// TIA Portal project "ISC_COMM_PROFINET_V15.1_rev1" (V15.1)
// Example of PLC to ISC-CAM communication.

(* hardware
DEVICE "S7-1200 station_1"  S7-1200 Station
   slot 0: "Rack_0"  S7-1200 Rack  Rack  V1.0
   slot 1: "LinePLC1"  CPU 1215C DC/DC/DC  6ES7 215-1AG40-0XB0  V4.2
DEVICE "ISC-CAM"  GSD.Device.PN
   slot 0: "Rack"  Rack  V1.0
   slot 0: "ISC-CAM_145"  Business Logic PN Device  SW V 1.6.3
      slot 0: "DAP v3.1"  DAP v3.1
      slot 1: "PN-IO"  PN-IO
         slot 1: "Port 1"  Port 1
         slot 2: "Port 2"  Port 2
   slot 1: "IN 48 WORD"  IN 48 WORD
      slot 0: "IN 48 WORD"  IN 48 WORD
   slot 2: "OUT 16 WORD"  OUT 16 WORD
      slot 0: "OUT 16 WORD"  OUT 16 WORD
DEVICE "ISC-CAM_1"  GSD.Device.PN
   slot 0: "Rack"  Rack  V1.0
   slot 0: "ISC-CAM_146"  Business Logic PN Device  SW V 1.6.3
      slot 0: "DAP v3.1"  DAP v3.1
      slot 1: "PN-IO"  PN-IO
         slot 1: "Port 1"  Port 1
         slot 2: "Port 2"  Port 2
   slot 1: "IN 48 WORD"  IN 48 WORD
      slot 0: "IN 48 WORD"  IN 48 WORD
   slot 2: "OUT 16 WORD"  OUT 16 WORD
      slot 0: "OUT 16 WORD"  OUT 16 WORD
*)

// ===== PLC "LinePLC1"  CPU 1215C DC/DC/DC =====

VAR_GLOBAL   // PLC tag table "Default tag table"
   "Sim_EncoderOutput(0)" AT %Q0.0 : Bool;
   "Sim_PEOutput(0)" AT %Q0.1 : Bool;
   "System_Byte" AT %MB1 : Byte;
   "FirstScan" AT %M1.0 : Bool;
   "DiagStatusUpdate" AT %M1.1 : Bool;
   "AlwaysTRUE" AT %M1.2 : Bool;
   "AlwaysFALSE" AT %M1.3 : Bool;
   "Clock_Byte" AT %MB0 : Byte;
   "Clock_10Hz" AT %M0.0 : Bool;
   "Clock_5Hz" AT %M0.1 : Bool;
   "Clock_2.5Hz" AT %M0.2 : Bool;
   "Clock_2Hz" AT %M0.3 : Bool;
   "Clock_1.25Hz" AT %M0.4 : Bool;
   "Clock_1Hz" AT %M0.5 : Bool;
   "Clock_0.625Hz" AT %M0.6 : Bool;
   "Clock_0.5Hz" AT %M0.7 : Bool;
   "Sim_EncoderOutput(1)" AT %Q0.2 : Bool;
   "Sim_PEOutput(1)" AT %Q0.3 : Bool;
END_VAR

VAR_GLOBAL CONSTANT   // PLC tag table "Default tag table"
   "ParameterNr" : DInt := 13;   // Number of parameters + 1
   "RecipeNr" : DInt := 3;   // Number of recipes + 1
END_VAR

TYPE "dt_ISCCAM"
   STRUCT
      Command : "dt_ISCCAM_Cmd";
      Status : "dt_ISCCAM_Stat";
      Parameter : "dt_ISCCAM_Parameter";
      Datacollection : "dt_ISCCAM_Datacollection";
      CommunicationHealthy : Bool;
   END_STRUCT;
END_TYPE

TYPE "dt_ISCCAM_Cmd"
   STRUCT
      LifeBit : Bool;   // Lifebit
      Reset_Error : Bool;   // Reset error
      MotorRunning : Bool;   // Motor running
      ProductsFromInfeed2 : Bool;   // Products from infeed 2
      AssignDestination : Int;   // Assign destination
      ExternalModel : Bool;   // External model
      Exit1BalancingSet : Int;   // Set balancing exit 1
      Exit2BalancingSet : Int;   // Set balancing exit 2
      Exit3BalancingSet : Int;   // Set balancing exit 3
      EndBalancingSet : Int;   // Set balancing end
      DES_Enable1 : Bool;   // Enable destination 1
      DES_Enable2 : Bool;   // Enable destination 2
      DES_Enable3 : Bool;   // Enable destination 3
   END_STRUCT;
END_TYPE

TYPE "dt_ISCCAM_Datacollection"
   STRUCT
      BeltRunTime : DInt;   // Cumulative time the belt is moving [min]
      BeltTravelDistance : DInt;   // Cumulative distance the belt has traveled [m]
      "ActivationCount Zone0" : DInt;   // Cumulative number of activations divert zone 0
      "ActivationCount Zone1" : DInt;   // Cumulative number of activations divert zone 1
      "ActivationCount Zone2" : DInt;   // Cumulative number of activations divert zone 2
      ProductCount : DInt;   // Cumulative number of products on the belt
      StartStops : DInt;   // Cumulative number of start stops of the belt
      GapToSmallCount : DInt;   // Cumulative number a too small gap was detected
      FaultCount : Int;   // A counter that keeps track of how many faults were detected
      MaxBeltSpeed : Int;   // The maximum belt speed that has been detected [m/min]
      PeakAcceleration : Int;   // Peak acceleration [m/min2]
      PeakDecceleration : Int;   // Peak decceleration [m/min2]
   END_STRUCT;
END_TYPE

TYPE "dt_ISCCAM_FaultCode"
   STRUCT
      "FaultCode.8" : Bool;   // Peg not seen when expected
      "FaultCode.9" : Bool;   // Gap for next product
      "FaultCode.10" : Bool;   // Too much or too low voltage from power supply
      "FaultCode.11" : Bool;   // IO Current fault. Input too high or too low (indicates short or cable disconnected)
      "FaultCode.12" : Bool;   // IO-Link error port C0
      "FaultCode.13" : Bool;   // IO-Link error port C1
      "FaultCode.14" : Bool;   // IO-Link error port C2
      "FaultCode.15" : Bool;   // IO-Link error port C3
      "FaultCode.0" : Bool;   // Line controller PLC indicated the drive motor is running, but the encoder does not detect motion
      "FaultCode.1" : Bool;   // Line controller PLC indicates the drive motor is off, but the encoder detects belt motion
      "FaultCode.2" : Bool;   // Belt detected to move too slow (and not stopped)
      "FaultCode.3" : Bool;   // Belt detected to move too fast
      "FaultCode.4" : Bool;   // Status of photoeye Product Sensor 1
      "FaultCode.5" : Bool;   // Status of photoeye Product Sensor 2 (Optional)
      "FaultCode.6" : Bool;   // Status of photoeye Product Sensor 3 (Optional)
      "FaultCode.7" : Bool;   // Peg sensor blocked continuously with belt moving
      "FaultCode.24" : Bool;
      "FaultCode.25" : Bool;
      "FaultCode.26" : Bool;
      "FaultCode.27" : Bool;
      "FaultCode.28" : Bool;
      "FaultCode.29" : Bool;
      "FaultCode.30" : Bool;
      "FaultCode.31" : Bool;
      "FaultCode.16" : Bool;
      "FaultCode.17" : Bool;
      "FaultCode.18" : Bool;
      "FaultCode.19" : Bool;
      "FaultCode.20" : Bool;
      "FaultCode.21" : Bool;
      "FaultCode.22" : Bool;
      "FaultCode.23" : Bool;
   END_STRUCT;
END_TYPE

TYPE "dt_ISCCAM_IO_Status"
   STRUCT
      "IO Status.8" : Bool;
      "IO Status.9" : Bool;
      "IO Status.10" : Bool;
      "IO Status.11" : Bool;
      "IO Status.12" : Bool;
      "IO Status.13" : Bool;
      "IO Status.14" : Bool;
      "IO Status.15" : Bool;
      "IO Status.0" : Bool;
      "IO Status.1" : Bool;   // Product sensor
      "IO Status.2" : Bool;   // Peg sensor divert 1 (AIM only)
      "IO Status.3" : Bool;   // Valve divert 1
      "IO Status.4" : Bool;   // Peg sensor divert 2 (AIM only)
      "IO Status.5" : Bool;   // Valve divert 2
      "IO Status.6" : Bool;   // Discrete divert Signal
      "IO Status.7" : Bool;   // Run/Error
   END_STRUCT;
END_TYPE

TYPE "dt_ISCCAM_Parameter"
   STRUCT
      Cmd : "dt_ISCCAM_Parameter_Cmd";
      Stat : "dt_ISCCAM_Parameter_Stat";
   END_STRUCT;
END_TYPE

TYPE "dt_ISCCAM_Parameter_Cmd"
   STRUCT
      ParameterNumber : Int;   // Parameter number f or read / write access.
      ParameterData : DWord;   // Parameter data f or write access.
      ReadTrigger : Bool;   // Read trigger.
      WriteTrigger : Bool;   // Write trigger.
   END_STRUCT;
END_TYPE

TYPE "dt_ISCCAM_Parameter_Stat"
   STRUCT
      ParameterNumber : Int;   // Parameter number feedback
      ParameterData : DWord;   // Parameter data
      ParameterReadSuccessfully : Bool;   // Parameter read successfully
      ParameterWriteSuccessfully : Bool;   // Parameter write successfully
      ParameterNumberNotExistReadOnly : Bool;   // Parameter number does not exist or is read only
      ParameterValueOutOfRange : Bool;   // Parameter value out of range
   END_STRUCT;
END_TYPE

TYPE "dt_ISCCAM_PI"
   STRUCT
      Status : "dt_ISCCAM_PI_Status";
      DataCollection1 : "dt_ISCCAM_PI_DataCollection_1";
      DataCollection2 : "dt_ISCCAM_PI_DataCollection_2";
   END_STRUCT;
END_TYPE

TYPE "dt_ISCCAM_PI_DataCollection_1"
   STRUCT
      BeltRunTime_MSW : Word;   // Cumulative time the belt is moving [min] HiWord
      BeltRunTime_LSW : Word;   // Cumulative time the belt is moving [min] LoWord
      BeltTravelDistance_MSW : Word;   // Cumulative distance the belt has traveled [m] HiWord
      BeltTravelDistance_LSW : Word;   // Cumulative distance the belt has traveled [m] LoWord
      ActivationCount_Zone0_MSW : Word;   // Cumulative number of activations divert zone 0 HiWord
      ActivationCount_Zone0_LSW : Word;   // Cumulative number of activations divert zone 0 LoWord
      ActivationCount_Zone1_MSW : Word;   // Cumulative number of activations divert zone 1 HiWord
      ActivationCount_Zone1_LSW : Word;   // Cumulative number of activations divert zone 1 LoWord
      ActivationCount_Zone2_MSW : Word;   // Cumulative number of activations divert zone 2 HiWord
      ActivationCount_Zone2_LSW : Word;   // Cumulative number of activations divert zone 2 LoWord
      ProductCount_MSW : Word;   // Cumulative number of products on the belt HiWord
      ProductCount_LSW : Word;   // Cumulative number of products on the belt LoWord
      StartStops_MSW : Word;   // Cumulative number of start stops of the belt HiWord
      StartStops_LSW : Word;   // Cumulative number of start stops of the belt LoWord
      GapToSmallCount_MSW : Word;   // Cumulative number a too small gap was detected HiWord
      GapToSmallCount_LSW : Word;   // Cumulative number a too small gap was detected LoWord
   END_STRUCT;
END_TYPE

TYPE "dt_ISCCAM_PI_DataCollection_2"
   STRUCT
      FaultCount : Word;   // A counter that keeps track of how many faults were detected
      MaxBeltSpeed : Word;   // The maximum belt speed that has been detected [m/min]
      PeakAcceleration : Word;   // Peak acceleration [m/min2]
      PeakDecceleration : Word;   // Peak decceleration [m/min2]
   END_STRUCT;
END_TYPE

TYPE "dt_ISCCAM_PI_Status"
   STRUCT
      EncoderStatus : Bool;   // Belt encoder pulses
      W0b9 : Bool;
      W0b10 : Bool;
      W0b11 : Bool;
      W0b12 : Bool;
      W0b13 : Bool;
      W0b14 : Bool;
      W0b15 : Bool;
      Life_Bit : Bool;   // Life bit / Heartbeat / Watchdog
      SystemReady : Bool;   // System Ready (no fault)
      W0b2 : Bool;
      W0b3 : Bool;
      Error : Bool;   // Error in Machine
      W0b5 : Bool;
      W0b6 : Bool;
      W0b7 : Bool;
      FaultCode : DWord;   // FaultCode
      ProductsOnBelt : Word;   // Count of current products on the belt
      Throughput : Word;   // Products on DPE
      BeltSpeed : Word;   // Current speed of the belt [m/min]
      BeltAcceleration : Word;   // Acceleration speed of the belt [m/min2]
      "IO Status" : Word;   // IO Status
      W8 : Word;
      "PowerON MSW" : Word;   // Time since the ISC is powered on [sec] HiWord
      "PowerON LSW" : Word;   // Time since the ISC is powered on [sec] LoWord
      W11 : Word;
      "Parameter number feedback" : Word;   // Parameter number
      W13b8 : Bool;
      W13b9 : Bool;
      W13b10 : Bool;
      W13b11 : Bool;
      W13b12 : Bool;
      W13b13 : Bool;
      W13b14 : Bool;
      W13b15 : Bool;
      "Parameter read successfully" : Bool;   // Parameter read ok
      "Parameter write successfully" : Bool;   // Parameter write ok
      "Parameter number not exist or read only" : Bool;   // Parameter ID number incorrect or read only
      "Parameter value is out of range" : Bool;   // Parameter value incorrect
      W13b4 : Bool;
      W13b5 : Bool;
      W13b6 : Bool;
      W13b7 : Bool;
      "Parameter data register High Word" : Word;   // Parameter Data MSW
      "Parameter data register Low Word" : Word;   // Parameter Data MSW
   END_STRUCT;
END_TYPE

TYPE "dt_ISCCAM_PO"
   STRUCT
      Command : "dt_ISCCAM_PO_Command";
   END_STRUCT;
END_TYPE

TYPE "dt_ISCCAM_PO_Command"
   STRUCT
      W0b8 : Bool;
      W0b9 : Bool;
      W0b10 : Bool;
      W0b11 : Bool;
      W0b12 : Bool;
      ProductsFromInfeed2 : Bool;   // Products from infeed 2
      W0b14 : Bool;
      W0b15 : Bool;
      Life_Bit : Bool;   // Life bit
      MotorRunning : Bool;   // Motor is running
      W0b2 : Bool;
      W0b3 : Bool;
      W0b4 : Bool;
      W0b5 : Bool;
      W0b6 : Bool;
      Reset_Error : Bool;   // Reset all errors
      "Divert destination" : Word;   // Divert destination of the next product that will be arriving on the belt (external mode only)
      RunMode : Word;   // Internal mode [0] or external mode [1]
      ProductCountExit0 : Word;   // Number of products to exit (internal mode only)
      ProductCountExit1 : Word;   // Number of products to exit (internal mode only)
      ProductCountExit2 : Word;   // Number of products to exit (internal mode only)
      ProductCountExit3 : Word;   // Number of products to exit (internal mode only)
      W7b8 : Bool;
      W7b9 : Bool;
      W7b10 : Bool;
      W7b11 : Bool;
      W7b12 : Bool;
      W7b13 : Bool;
      W7b14 : Bool;
      W7b15 : Bool;
      "Enable exit 1" : Bool;   // Destination Enable/Disable
      "Enable exit 2" : Bool;   // Destination Enable/Disable
      "Enable exit 3" : Bool;   // Destination Enable/Disable
      W7b3 : Bool;
      W7b4 : Bool;
      W7b5 : Bool;
      W7b6 : Bool;
      W7b7 : Bool;
      W8 : Word;
      W9 : Word;
      W10 : Word;
      W11 : Word;
      "Parameter number for read / write access" : Word;   // Parameter number
      W13b8 : Bool;
      W13b9 : Bool;
      W13b10 : Bool;
      W13b11 : Bool;
      W13b12 : Bool;
      W13b13 : Bool;
      W13b14 : Bool;
      W13b15 : Bool;
      "Read Parameter" : Bool;   // Read parameter
      "Write Parameter" : Bool;   // Write parameter
      W13b2 : Bool;
      W13b3 : Bool;
      W13b4 : Bool;
      W13b5 : Bool;
      W13b6 : Bool;
      W13b7 : Bool;
      "Parameter data register High Word" : Word;   // Parameter Data MSW
      "Parameter data register Low Word" : Word;   // Parameter Data LSW
   END_STRUCT;
END_TYPE

TYPE "dt_ISCCAM_Stat"
   STRUCT
      LifeBit : Bool;   // Lifebit
      SystemReady : Bool;   // System ready
      Error : Bool;   // Error
      FaultCode : "dt_ISCCAM_FaultCode";   // Fault code
      ProductsOnBelt : Int;   // Products on belt
      Throughput : Int;   // Throughput
      BeltSpeed : Int;   // Belt speed
      BeltAcceleration : Int;   // Belt acceleration
      IOstatus : "dt_ISCCAM_IO_Status";   // IO status
      UpTime : DInt;   // Up time in min
   END_STRUCT;
END_TYPE

TYPE "dt_ISCCAM_Alarms"
   STRUCT
      CommsAlarm : Bool;   // Communication to ISC not healthy.
      Fault8Alarm : Bool;   // Peg not seen when expected
      Fault9Alarm : Bool;   // Gap for next product
      Fault10Alarm : Bool;   // Too much or too low voltage from power supply
      Fault11Alarm : Bool;   // IO Current fault, input too high or too low (indicates short or cable disconnected)
      Fault12Alarm : Bool;   // IO-Link error port C0
      Fault13Alarm : Bool;   // IO-Link error port C1
      Fault14Alarm : Bool;   // IO-Link error port C2
      Fault15Alarm : Bool;   // IO-Link error port C3
      Fault0Alarm : Bool;   // Line controller PLC indicated the motor is running. But the encoder does not detect motion
      Fault1Alarm : Bool;   // Line controller PLC indicates the drive motor is off, but the encoder detects belt motion
      Fault2Alarm : Bool;   // Belt detected to move too slow (and not stopped)
      Fault3Alarm : Bool;   // Belt detected to move too fast
      Fault4Alarm : Bool;   // Status of photoeye Product Sensor 1
      Fault5Alarm : Bool;   // Status of photoeye Product Sensor 2 (Optional)
      Fault6Alarm : Bool;   // Status of photoeye Product Sensor 3 (Optional)
      Fault7Alarm : Bool;   // Peg sensor blocked continuously with belt moving
   END_STRUCT;
END_TYPE

TYPE "dt_ISCCAM_Maintenance"
   STRUCT
      Counters : Array[0..15] of "dt_ISCCAM_MaintenanceCounter";
   END_STRUCT;
   // // Counters[0] : Belt run time - belt elongation.
   // // Counters[1] : Belt run time - belt contaminants.
   // // Counters[2] : Belt run time - wearstrip thickness.
   // // Counters[3] : Belt run time - helix rollers.
   // // Counters[4] : Belt run time - transfer rollers.
   // // Counters[5] : Belt run time - return rollers.
   // // Counters[6] : Belt run time - oil level drive motor.
   // // Counters[7] : Belt run time - cylinder movement, wear and contaminants, zone 0
   // // Counters[8] : Belt run time - cylinder movement, wear and contaminants, zone 1
   // // Counters[9] : Belt run time - cylinder movement, wear and contaminants, zone 2
   // // Counters[10] : Belt run time - pneumatic system check.
   // // Counters[11] : Spare
   // // Counters[12] : Spare
   // // Counters[13] : Spare
   // // Counters[14] : Spare
   // // Counters[15] : Spare
END_TYPE

TYPE "dt_ISCCAM_MaintenanceCounter"
   STRUCT
      Reset : Bool;   // Reset warning
      WarningBit : Bool;   // Warning active
      MaintenanceThreshold : DInt;   // Threshold to create warning [h]
      MaintenanceCountUnitlNextMaintenance : DInt;   // Count until next maintenance [min]
   END_STRUCT;
END_TYPE

// folder: Recipe

TYPE "dt_Rec_ISCCAM_Parameter"
   STRUCT
      ID : Int;
      Description : String;
   END_STRUCT;
END_TYPE

TYPE "dt_Rec_ISCCAM_Recipe"
   STRUCT
      "Name" : String;
      Parameter : Array[0.."ParameterNr"] of "dt_Rec_ISCCAM_Recipe_Parameter";
   END_STRUCT;
END_TYPE

TYPE "dt_Rec_ISCCAM_Recipe_Header"
   STRUCT
      "Name" : String;
      Number : DInt;
   END_STRUCT;
END_TYPE

TYPE "dt_Rec_ISCCAM_Recipe_Parameter"
   STRUCT
      ID : Int;
      "Name" : String;
      Description : String;
      Value : DInt;
   END_STRUCT;
END_TYPE

TYPE "dt_Rec_M001_Recipe"
   STRUCT
      Header : "dt_Rec_ISCCAM_Recipe_Header";
      Machine_001 : "dt_Rec_Machine_Recipe_Parameter";
   END_STRUCT;
END_TYPE

TYPE "dt_Rec_M002_Recipe"
   STRUCT
      Header : "dt_Rec_ISCCAM_Recipe_Header";
      Machine_002 : "dt_Rec_Machine_Recipe_Parameter";
   END_STRUCT;
END_TYPE

TYPE "dt_Rec_Machine_Recipe_Parameter"
   STRUCT
      Parameter : Array[0.."ParameterNr"] of "dt_Rec_ISCCAM_Recipe_Parameter";
   END_STRUCT;
END_TYPE

TYPE "dt_Rec_Recipe"
   STRUCT
      Header : "dt_Rec_ISCCAM_Recipe_Header";
      M001 : "dt_Rec_Machine_Recipe_Parameter";
      M002 : "dt_Rec_Machine_Recipe_Parameter";
   END_STRUCT;
END_TYPE

// folder: (top level)

DATA_BLOCK "DB_Global"   // DB4
{ S7_Optimized_Access := 'TRUE' }
VERSION : 0.1
   VAR
      InitRecipe : Bool;
      myLADDR : Hw_IoSystem;
      myMODE : UInt;
      returnValue : Int;
      mySTATE : Array[0..1023] of Bool;
   END_VAR
BEGIN
END_DATA_BLOCK

// folder: 000-099_General

DATA_BLOCK "iDB_General_Diagnostics"   // DB2
{ S7_Optimized_Access := 'TRUE' }
VERSION : 0.1
"General_Diagnostics"
BEGIN
END_DATA_BLOCK

DATA_BLOCK "iDB_General_Main"   // DB3
{ S7_Optimized_Access := 'TRUE' }
VERSION : 0.1
"General_Main"
BEGIN
END_DATA_BLOCK

DATA_BLOCK "DB_General_HMI"   // DB8
{ S7_Optimized_Access := 'TRUE' }
VERSION : 0.1
   VAR
      GeneralDateTimePLC : DTL;
      GeneralHmiSNPointer : Array[0..4] of Word;
      GeneralHMIScreenNumber : Int;
      GeneralFaultBits : Array[0..7] of Word;
      GeneralFaultGroupBits : Word;
      GeneralFault : Bool;
      GeneralAlarmBtnCol : Int;
      GeneralResetBtnCmd : Bool;
      AlarmBtnCol : Int;
      MaintenanceBtnCol : Int;
   END_VAR
BEGIN
END_DATA_BLOCK

// folder: 100-199_Machine_001

DATA_BLOCK "DB_M001_Status"   // DB11
{ S7_Optimized_Access := 'TRUE' }
VERSION : 0.1
   VAR
      "ISC-CAM" : "dt_ISCCAM";
   END_VAR
BEGIN
END_DATA_BLOCK

DATA_BLOCK "DB_M001_HMI"   // DB12
{ S7_Optimized_Access := 'TRUE' }
VERSION : 0.1
   VAR
      FaultBits : "dt_ISCCAM_Alarms";
      Fault : Bool;   // Any fault present
      MaintenanceCounters : "dt_ISCCAM_Maintenance";
   END_VAR
BEGIN
END_DATA_BLOCK

DATA_BLOCK "iDB_M001_Main"   // DB13
{ S7_Optimized_Access := 'TRUE' }
VERSION : 0.1
"M001_Main"
BEGIN
END_DATA_BLOCK

// folder: 200-299_Machine_002

DATA_BLOCK "DB_M002_Status"   // DB5
{ S7_Optimized_Access := 'TRUE' }
VERSION : 0.1
   VAR
      "ISC-CAM" : "dt_ISCCAM";
   END_VAR
BEGIN
END_DATA_BLOCK

DATA_BLOCK "iDB_M002_Main"   // DB6
{ S7_Optimized_Access := 'TRUE' }
VERSION : 0.1
"M002_Main"
BEGIN
END_DATA_BLOCK

DATA_BLOCK "DB_M002_HMI"   // DB9
{ S7_Optimized_Access := 'TRUE' }
VERSION : 0.1
   VAR
      FaultBits : "dt_ISCCAM_Alarms";
      Fault : Bool;   // Any fault present
      MaintenanceCounters : "dt_ISCCAM_Maintenance";
   END_VAR
BEGIN
END_DATA_BLOCK

// folder: (top level)

ORGANIZATION_BLOCK "Main"   // OB1, LAD, ProgramCycle
TITLE = "Main Program Sweep (Cycle)"
{ S7_Optimized_Access := 'TRUE' }
AUTHOR : Intralox
VERSION : 0.1
BEGIN

REGION Network 1
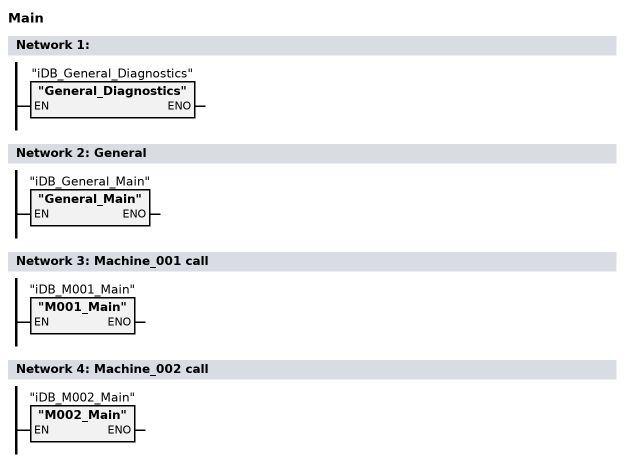
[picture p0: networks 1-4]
   RUNG wire#powerrail
      "iDB_General_Diagnostics"()
   END_RUNG
   // the same network as SCL:
   "iDB_General_Diagnostics"();   // "General_Diagnostics"
END_REGION

REGION Network 2: General
   RUNG wire#powerrail
      "iDB_General_Main"()
   END_RUNG
   // the same network as SCL:
   "iDB_General_Main"();   // "General_Main"
END_REGION

REGION Network 3: Machine_001 call
   RUNG wire#powerrail
      "iDB_M001_Main"()
   END_RUNG
   // the same network as SCL:
   "iDB_M001_Main"();   // "M001_Main"
END_REGION

REGION Network 4: Machine_002 call
   RUNG wire#powerrail
      "iDB_M002_Main"()
   END_RUNG
   // the same network as SCL:
   "iDB_M002_Main"();   // "M002_Main"
END_REGION
END_ORGANIZATION_BLOCK

ORGANIZATION_BLOCK "Startup"   // OB100, LAD, Startup
TITLE = "Complete Restart"
{ S7_Optimized_Access := 'TRUE' }
VERSION : 0.1
   VAR_INPUT
      LostRetentive : Bool;   // True if retentive data are lost
      LostRTC : Bool;   // True if date and time are lost
   END_VAR
BEGIN

REGION Network 1 (SCL): M001 Maintenance Thressholds
   IF "DB_M001_HMI".MaintenanceCounters.Counters[0].MaintenanceThreshold = 0 THEN
       "DB_M001_HMI".MaintenanceCounters.Counters[0].MaintenanceThreshold := 8000;
   END_IF;

   IF "DB_M001_HMI".MaintenanceCounters.Counters[1].MaintenanceThreshold = 0 THEN
       "DB_M001_HMI".MaintenanceCounters.Counters[1].MaintenanceThreshold := 8000;
   END_IF;

   IF "DB_M001_HMI".MaintenanceCounters.Counters[2].MaintenanceThreshold = 0 THEN
       "DB_M001_HMI".MaintenanceCounters.Counters[2].MaintenanceThreshold := 8000;
   END_IF;

   IF "DB_M001_HMI".MaintenanceCounters.Counters[3].MaintenanceThreshold = 0 THEN
       "DB_M001_HMI".MaintenanceCounters.Counters[3].MaintenanceThreshold := 8000;
   END_IF;

   IF "DB_M001_HMI".MaintenanceCounters.Counters[4].MaintenanceThreshold = 0 THEN
       "DB_M001_HMI".MaintenanceCounters.Counters[4].MaintenanceThreshold := 8000;
   END_IF;

   IF "DB_M001_HMI".MaintenanceCounters.Counters[5].MaintenanceThreshold = 0 THEN
       "DB_M001_HMI".MaintenanceCounters.Counters[5].MaintenanceThreshold := 16000;
   END_IF;

   IF "DB_M001_HMI".MaintenanceCounters.Counters[6].MaintenanceThreshold = 0 THEN
       "DB_M001_HMI".MaintenanceCounters.Counters[6].MaintenanceThreshold := 16000;
   END_IF;

   IF "DB_M001_HMI".MaintenanceCounters.Counters[7].MaintenanceThreshold = 0 THEN
       "DB_M001_HMI".MaintenanceCounters.Counters[7].MaintenanceThreshold := 8000;
   END_IF;

   IF "DB_M001_HMI".MaintenanceCounters.Counters[8].MaintenanceThreshold = 0 THEN
       "DB_M001_HMI".MaintenanceCounters.Counters[8].MaintenanceThreshold := 8000;
   END_IF;

   IF "DB_M001_HMI".MaintenanceCounters.Counters[9].MaintenanceThreshold = 0 THEN
       "DB_M001_HMI".MaintenanceCounters.Counters[9].MaintenanceThreshold := 8000;
   END_IF;

   IF "DB_M001_HMI".MaintenanceCounters.Counters[10].MaintenanceThreshold = 0 THEN
       "DB_M001_HMI".MaintenanceCounters.Counters[10].MaintenanceThreshold := 16000;
   END_IF;
END_REGION

REGION Network 2 (SCL): M002 Maintenance Thressholds
   IF "DB_M002_HMI".MaintenanceCounters.Counters[0].MaintenanceThreshold = 0 THEN
       "DB_M002_HMI".MaintenanceCounters.Counters[0].MaintenanceThreshold := 8000;
   END_IF;

   IF "DB_M002_HMI".MaintenanceCounters.Counters[1].MaintenanceThreshold = 0 THEN
       "DB_M002_HMI".MaintenanceCounters.Counters[1].MaintenanceThreshold := 8000;
   END_IF;

   IF "DB_M002_HMI".MaintenanceCounters.Counters[2].MaintenanceThreshold = 0 THEN
       "DB_M002_HMI".MaintenanceCounters.Counters[2].MaintenanceThreshold := 8000;
   END_IF;

   IF "DB_M002_HMI".MaintenanceCounters.Counters[3].MaintenanceThreshold = 0 THEN
       "DB_M002_HMI".MaintenanceCounters.Counters[3].MaintenanceThreshold := 8000;
   END_IF;

   IF "DB_M002_HMI".MaintenanceCounters.Counters[4].MaintenanceThreshold = 0 THEN
       "DB_M002_HMI".MaintenanceCounters.Counters[4].MaintenanceThreshold := 8000;
   END_IF;

   IF "DB_M002_HMI".MaintenanceCounters.Counters[5].MaintenanceThreshold = 0 THEN
       "DB_M002_HMI".MaintenanceCounters.Counters[5].MaintenanceThreshold := 16000;
   END_IF;

   IF "DB_M002_HMI".MaintenanceCounters.Counters[6].MaintenanceThreshold = 0 THEN
       "DB_M002_HMI".MaintenanceCounters.Counters[6].MaintenanceThreshold := 16000;
   END_IF;

   IF "DB_M002_HMI".MaintenanceCounters.Counters[7].MaintenanceThreshold = 0 THEN
       "DB_M002_HMI".MaintenanceCounters.Counters[7].MaintenanceThreshold := 8000;
   END_IF;

   IF "DB_M002_HMI".MaintenanceCounters.Counters[8].MaintenanceThreshold = 0 THEN
       "DB_M002_HMI".MaintenanceCounters.Counters[8].MaintenanceThreshold := 8000;
   END_IF;

   IF "DB_M002_HMI".MaintenanceCounters.Counters[9].MaintenanceThreshold = 0 THEN
       "DB_M002_HMI".MaintenanceCounters.Counters[9].MaintenanceThreshold := 8000;
   END_IF;

   IF "DB_M002_HMI".MaintenanceCounters.Counters[10].MaintenanceThreshold = 0 THEN
       "DB_M002_HMI".MaintenanceCounters.Counters[10].MaintenanceThreshold := 16000;
   END_IF;
END_REGION
END_ORGANIZATION_BLOCK

// folder: 000-099_General

FUNCTION_BLOCK "General_Diagnostics"   // FB10, LAD
TITLE = Diagnostics
{ S7_Optimized_Access := 'TRUE' }
VERSION : 0.1
BEGIN

REGION Network 1: Settings
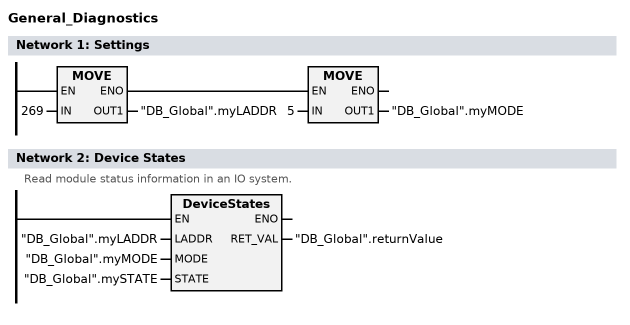
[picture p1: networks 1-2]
   RUNG wire#powerrail
      Move(in := 269, out1 => "DB_Global".myLADDR)
      Move(in := 5, out1 => "DB_Global".myMODE)
   END_RUNG
   // the same network as SCL:
   "DB_Global".myLADDR := 269;
   "DB_Global".myMODE := 5;
END_REGION

REGION Network 2: Device States
   // Read module status information in an IO system.
   // no SCL statement known for DeviceStates: written as a call
   "DB_Global".returnValue := DeviceStates(LADDR := "DB_Global".myLADDR,
                           MODE := "DB_Global".myMODE,
                           STATE := "DB_Global".mySTATE);
END_REGION
END_FUNCTION_BLOCK

FUNCTION_BLOCK "General_Faults"   // FB11, LAD
{ S7_Optimized_Access := 'TRUE' }
VERSION : 0.1
   VAR
      sBool : Bool;
   END_VAR
BEGIN

REGION Network 1 (SCL)
   // General fault indicator.
   "DB_General_HMI".GeneralFault := "DB_General_HMI".GeneralFaultGroupBits <> 0;
END_REGION
END_FUNCTION_BLOCK

FUNCTION_BLOCK "General_HMI"   // FB12, LAD
TITLE = General HMI
{ S7_Optimized_Access := 'TRUE' }
VERSION : 0.1
   VAR
      sBool : Bool;
   END_VAR
BEGIN

REGION Network 1 (SCL): Main alarm button color.
   // Fault color.
   IF "DB_General_HMI".GeneralFault OR
       "DB_M001_HMI".Fault  THEN
       "DB_General_HMI".GeneralAlarmBtnCol := 1;
       // Maintenance color.
   ELSIF
       "DB_M001_HMI".MaintenanceCounters.Counters[0].WarningBit <> 0 OR "DB_M001_HMI".MaintenanceCounters.Counters[1].WarningBit <> 0 OR
       "DB_M002_HMI".MaintenanceCounters.Counters[0].WarningBit <> 0 OR "DB_M002_HMI".MaintenanceCounters.Counters[1].WarningBit <> 0 THEN
       "DB_General_HMI".GeneralAlarmBtnCol := 3;
       // No color.
   ELSE
       "DB_General_HMI".GeneralAlarmBtnCol := 0;
   END_IF;
END_REGION

REGION Network 2 (SCL): Reset button.
   "DB_General_HMI".GeneralResetBtnCmd := "DB_General_HMI".GeneralResetBtnCmd; // Dummie
END_REGION

REGION Network 3 (SCL): Alarm button color.
   // Fault color.
   IF "DB_General_HMI".GeneralFault OR
       "DB_M001_HMI".Fault THEN
       "DB_General_HMI".AlarmBtnCol := 1;
       // No color.
   ELSE
       "DB_General_HMI".AlarmBtnCol := 0;
   END_IF;
END_REGION

REGION Network 4 (SCL): Maintenance button color.
   // Fault color.
   IF "DB_M001_HMI".MaintenanceCounters.Counters[0].WarningBit <> 0 OR "DB_M001_HMI".MaintenanceCounters.Counters[1].WarningBit <> 0 OR
       "DB_M002_HMI".MaintenanceCounters.Counters[0].WarningBit <> 0 OR "DB_M002_HMI".MaintenanceCounters.Counters[1].WarningBit <> 0 THEN
       "DB_General_HMI".MaintenanceBtnCol := 3;
       // No color.
   ELSE
       "DB_General_HMI".MaintenanceBtnCol := 0;
   END_IF;
END_REGION
END_FUNCTION_BLOCK

FUNCTION_BLOCK "General_Main"   // FB13, LAD
TITLE = General_Main, call the general sub routines from here.
{ S7_Optimized_Access := 'TRUE' }
VERSION : 0.1
   VAR
      General_Faults : "General_Faults";
      General_HMI : "General_HMI";
   END_VAR
BEGIN

REGION Network 1
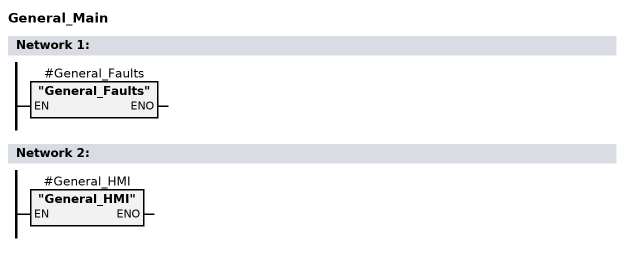
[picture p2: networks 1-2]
   RUNG wire#powerrail
      #General_Faults()
   END_RUNG
   // the same network as SCL:
   #General_Faults();   // "General_Faults"
END_REGION

REGION Network 2
   RUNG wire#powerrail
      #General_HMI()
   END_RUNG
   // the same network as SCL:
   #General_HMI();   // "General_HMI"
END_REGION
END_FUNCTION_BLOCK

FUNCTION "FC_Check8Bits" : Bool   // FC3, SCL
{ S7_Optimized_Access := 'TRUE' }
VERSION : 0.1
   VAR_INPUT
      b0 : Bool;
      b1 : Bool;
      b2 : Bool;
      b3 : Bool;
      b4 : Bool;
      b5 : Bool;
      b6 : Bool;
      b7 : Bool;
   END_VAR
   VAR_TEMP
      MemWord : Word;
   END_VAR
BEGIN
   // Input bits into a Word.
   #MemWord.%X0 := #b0;
   #MemWord.%X1 := #b1;
   #MemWord.%X2 := #b2;
   #MemWord.%X3 := #b3;
   #MemWord.%X4 := #b4;
   #MemWord.%X5 := #b5;
   #MemWord.%X6 := #b6;
   #MemWord.%X7 := #b7;

   // Make double sure to drop the first byte.
   #MemWord := #MemWord AND 16#00FF;

   // Check if multiple bits are set.
   IF (#MemWord AND INT_TO_WORD((WORD_TO_INT(#MemWord) * -1))) = #MemWord THEN
       #FC_Check8Bits := true;
   ELSE
       #FC_Check8Bits := false;
   END_IF;
END_FUNCTION

FUNCTION "FC_CheckMultipleBits" : Bool   // FC4, SCL
{ S7_Optimized_Access := 'TRUE' }
VERSION : 0.1
   VAR_INPUT
      Input : Word;
   END_VAR
BEGIN

   // Check if multiple bits are set.
   IF (#Input AND INT_TO_WORD((WORD_TO_INT(#Input) * -1))) = #Input THEN
       #FC_CheckMultipleBits := true;
   ELSE
       #FC_CheckMultipleBits := false;
   END_IF;
END_FUNCTION

FUNCTION "FC_DropSign" : String   // FC5, SCL
{ S7_Optimized_Access := 'TRUE' }
VERSION : 0.1
   VAR_INPUT
      IN_STR : String;
   END_VAR
   VAR_TEMP
      PlusPos : Int;
      NegPos : Int;
   END_VAR
BEGIN
   #PlusPos := FIND(IN1 := #IN_STR, IN2 := '+');
   #NegPos := FIND(IN1 := #IN_STR, IN2 := '-');

   IF #PlusPos > 0 THEN
       #FC_DropSign := DELETE(IN := #IN_STR, L := 1, P := #PlusPos);
   ELSIF #NegPos > 0 THEN
       #FC_DropSign := DELETE(IN := #IN_STR, L := 1, P := #NegPos);
   ELSE
       #FC_DropSign := #IN_STR;
   END_IF;
END_FUNCTION

// folder: 000-099_General/Auxiliary sensors

FUNCTION_BLOCK "Auxiliary sensors"   // FB2, LAD
{ S7_Optimized_Access := 'TRUE' }
VERSION : 0.1
   VAR_INPUT
      iPressureSwitch : Bool := true;
      iBeltElongationInfeed1 : Bool := true;
      iBeltElongationInfeed2 : Bool := true;
      iBeltElongationOutfeed1 : Bool := true;
      iBeltElongationOutfeed2 : Bool := true;
      iJamSensorInfeed : Bool := true;
      iJamSensorOutfeed : Bool := true;
      iBeltDisengagement : Bool := true;
      iDebris : Bool := true;
      iReset : Bool;
      iJamSensor1Time : Time := T#10ms;   // Time to trigger jam
      iJamSensor2Time : Time := T#10ms;   // Time to trigger jam
      iBeltRunning : Bool;   // Belt is running signal
   END_VAR
   VAR_OUTPUT
      oAlarms : Array[0..8] of Bool;
   END_VAR
   VAR
      JamSensor1Timer : TON_TIME;
      JamSensor2Timer : TON_TIME;
   END_VAR
   // start values inside typed variables
   // // oAlarms[0] : Air pressure fault
   // // oAlarms[1] : Too much belt elongation detected infeed 1
   // // oAlarms[2] : Too much belt elongation detected infeed 2
   // // oAlarms[3] : Too much belt elongation detected outfeed 1
   // // oAlarms[4] : Too much belt elongation detected outfeed 2
   // // oAlarms[5] : Jam detected in infeed
   // // oAlarms[6] : Jam detected in outfeed
   // // oAlarms[7] : Belt disengagement detected
   // // oAlarms[8] : Debris detected
BEGIN

REGION Network 1: Reset alarms
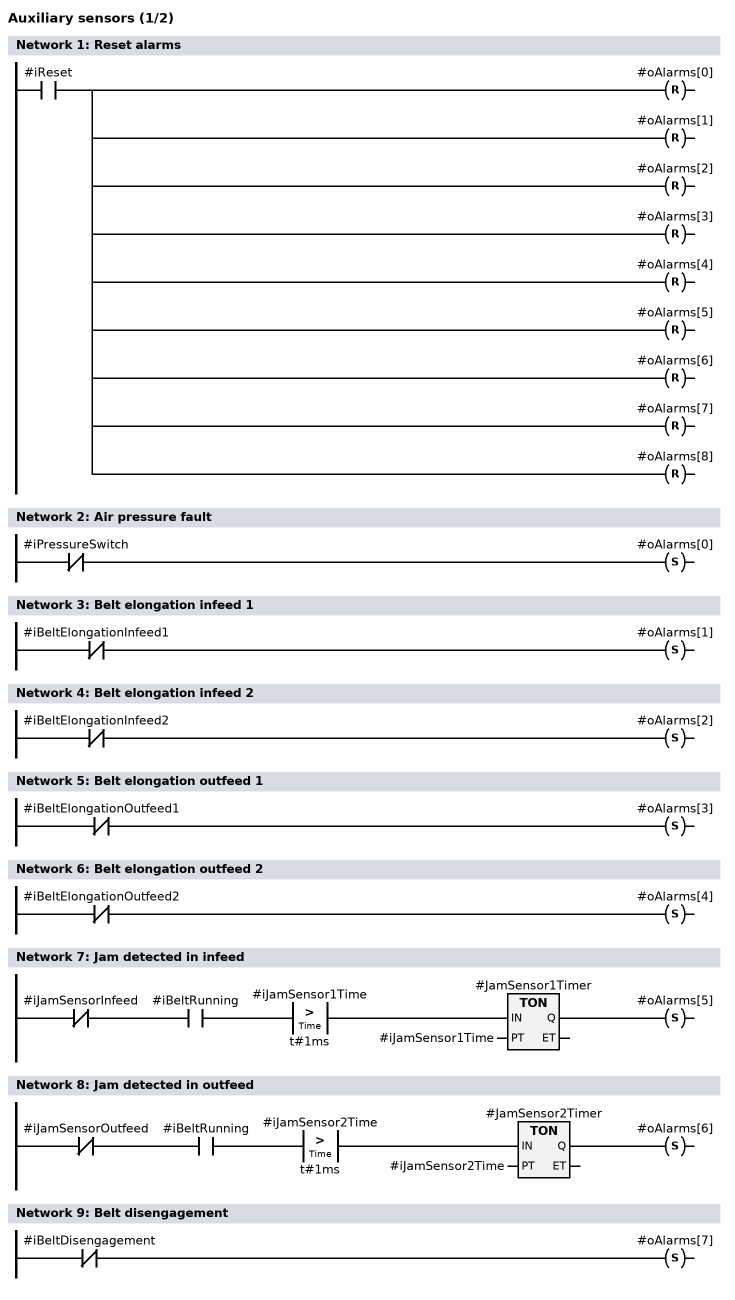
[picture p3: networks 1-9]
   RUNG wire#powerrail
      Contact( #iReset )
      wire#w1
      R_Coil( #oAlarms[0] )
   END_RUNG
   RUNG wire#w1
      R_Coil( #oAlarms[1] )
   END_RUNG
   RUNG wire#w1
      R_Coil( #oAlarms[2] )
   END_RUNG
   RUNG wire#w1
      R_Coil( #oAlarms[3] )
   END_RUNG
   RUNG wire#w1
      R_Coil( #oAlarms[4] )
   END_RUNG
   RUNG wire#w1
      R_Coil( #oAlarms[5] )
   END_RUNG
   RUNG wire#w1
      R_Coil( #oAlarms[6] )
   END_RUNG
   RUNG wire#w1
      R_Coil( #oAlarms[7] )
   END_RUNG
   RUNG wire#w1
      R_Coil( #oAlarms[8] )
   END_RUNG
   // the same network as SCL:
   IF #iReset THEN
       #oAlarms[0] := FALSE;
       #oAlarms[1] := FALSE;
       #oAlarms[2] := FALSE;
       #oAlarms[3] := FALSE;
       #oAlarms[4] := FALSE;
       #oAlarms[5] := FALSE;
       #oAlarms[6] := FALSE;
       #oAlarms[7] := FALSE;
       #oAlarms[8] := FALSE;
   END_IF;
END_REGION

REGION Network 2: Air pressure fault
   RUNG wire#powerrail
      I_Contact( #iPressureSwitch )
      S_Coil( #oAlarms[0] )
   END_RUNG
   // the same network as SCL:
   IF NOT #iPressureSwitch THEN #oAlarms[0] := TRUE; END_IF;
END_REGION

REGION Network 3: Belt elongation infeed 1
   RUNG wire#powerrail
      I_Contact( #iBeltElongationInfeed1 )
      S_Coil( #oAlarms[1] )
   END_RUNG
   // the same network as SCL:
   IF NOT #iBeltElongationInfeed1 THEN #oAlarms[1] := TRUE; END_IF;
END_REGION

REGION Network 4: Belt elongation infeed 2
   RUNG wire#powerrail
      I_Contact( #iBeltElongationInfeed2 )
      S_Coil( #oAlarms[2] )
   END_RUNG
   // the same network as SCL:
   IF NOT #iBeltElongationInfeed2 THEN #oAlarms[2] := TRUE; END_IF;
END_REGION

REGION Network 5: Belt elongation outfeed 1
   RUNG wire#powerrail
      I_Contact( #iBeltElongationOutfeed1 )
      S_Coil( #oAlarms[3] )
   END_RUNG
   // the same network as SCL:
   IF NOT #iBeltElongationOutfeed1 THEN #oAlarms[3] := TRUE; END_IF;
END_REGION

REGION Network 6: Belt elongation outfeed 2
   RUNG wire#powerrail
      I_Contact( #iBeltElongationOutfeed2 )
      S_Coil( #oAlarms[4] )
   END_RUNG
   // the same network as SCL:
   IF NOT #iBeltElongationOutfeed2 THEN #oAlarms[4] := TRUE; END_IF;
END_REGION

REGION Network 7: Jam detected in infeed
   #JamSensor1Timer(IN := NOT #iJamSensorInfeed AND #iBeltRunning AND (#iJamSensor1Time > t#1ms),   // TON
                    PT := #iJamSensor1Time);
   IF #JamSensor1Timer.Q THEN #oAlarms[5] := TRUE; END_IF;
END_REGION

REGION Network 8: Jam detected in outfeed
   #JamSensor2Timer(IN := NOT #iJamSensorOutfeed AND #iBeltRunning AND (#iJamSensor2Time > t#1ms),   // TON
                    PT := #iJamSensor2Time);
   IF #JamSensor2Timer.Q THEN #oAlarms[6] := TRUE; END_IF;
END_REGION

REGION Network 9: Belt disengagement
   RUNG wire#powerrail
      I_Contact( #iBeltDisengagement )
      S_Coil( #oAlarms[7] )
   END_RUNG
   // the same network as SCL:
   IF NOT #iBeltDisengagement THEN #oAlarms[7] := TRUE; END_IF;
END_REGION

REGION Network 10: Debris
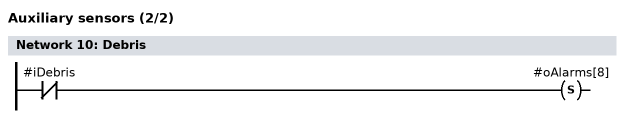
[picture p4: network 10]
   RUNG wire#powerrail
      I_Contact( #iDebris )
      S_Coil( #oAlarms[8] )
   END_RUNG
   // the same network as SCL:
   IF NOT #iDebris THEN #oAlarms[8] := TRUE; END_IF;
END_REGION
END_FUNCTION_BLOCK

// folder: 000-099_General/ISC

FUNCTION_BLOCK "FB_ISC-CAM_Comm"   // FB9, LAD
{ S7_Optimized_Access := 'FALSE' }
VERSION : 0.1
   VAR_INPUT
      HW_Inputs_ID : Hw_SubModule;   // HW ID for the inputs can be found under the system constants
      HW_Outputs_ID : Hw_SubModule;   // HW ID for the outputs can be found under the system constants
      Command : "dt_ISCCAM_Cmd";
   END_VAR
   VAR_OUTPUT
      Status : "dt_ISCCAM_Stat";
      DataCollection : "dt_ISCCAM_Datacollection";
   END_VAR
   VAR_IN_OUT
      Parameter : "dt_ISCCAM_Parameter";
   END_VAR
   VAR
      GETIO_Instance : GETIO;   // GETIO instance
      SETIO_Instance : SETIO;   // SETIO instance
      PIData : Array[0..47] of Word;   // PI Data
      stPIData AT PIData : "dt_ISCCAM_PI";   // PI Data memory overlay
      POData : Array[0..15] of Word;   // PO Data
      stPOData AT POData : "dt_ISCCAM_PO";   // PO Data memory overlay
      testWord : Word;
      testboolArray AT testWord : Array[0..15] of Bool;
      testEndBoolArray : Array[0..15] of Bool;
   END_VAR
   VAR_TEMP
      tWord1 : DWord;
      tWord2 : DWord;
      tWord3 : DWord;   // PI
      tWord4 : DWord;
      test : Bool;
      testbyte0 : Byte;
      testbyte1 : Byte;
      tempFaultCode : DWord;
      tempFaultCodeOut AT tempFaultCode : "dt_ISCCAM_FaultCode";
      tempIOStatus : Word;
      tempIOStatusOut AT tempIOStatus : "dt_ISCCAM_IO_Status";
   END_VAR
   VAR_TEMP   // added for the SCL form of the ladder/FBD networks
      _w1 : Bool;
   END_VAR
BEGIN

REGION Network 1: Read PI data.
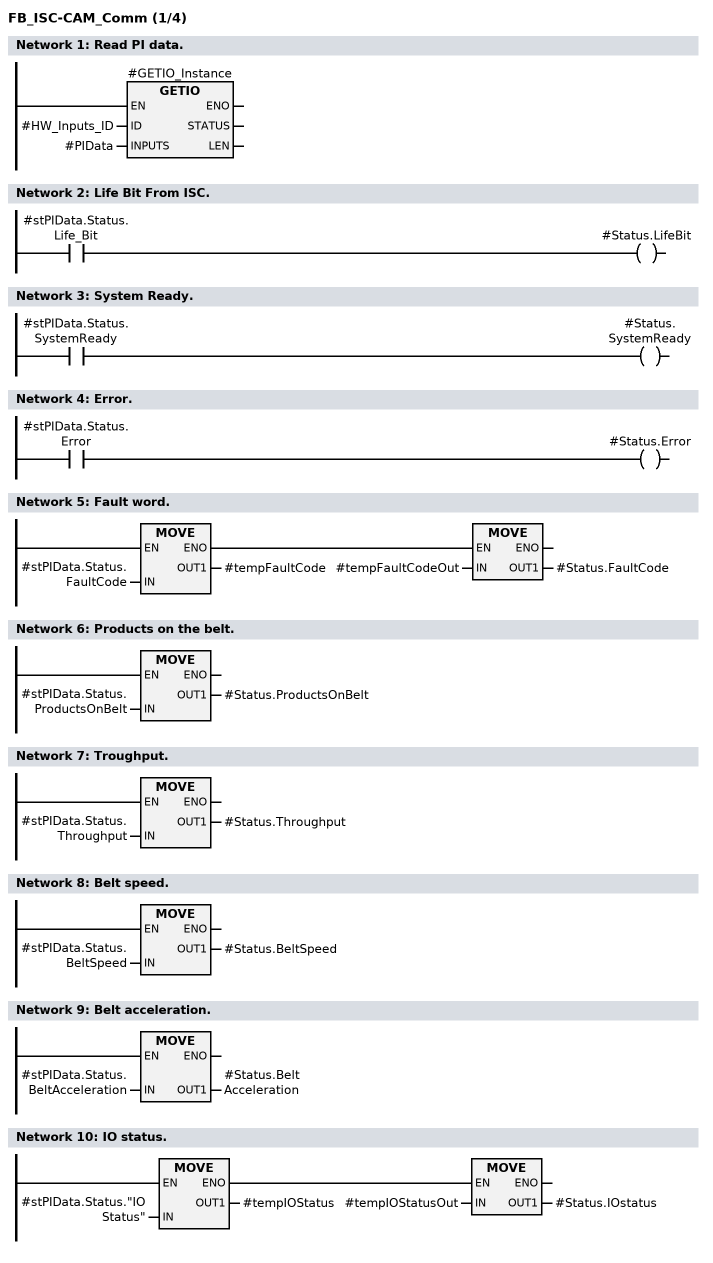
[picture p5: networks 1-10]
   #GETIO_Instance(ID := #HW_Inputs_ID, INPUTS := #PIData);   // GETIO
END_REGION

REGION Network 2: Life Bit From ISC.
   RUNG wire#powerrail
      Contact( #stPIData.Status.Life_Bit )
      Coil( #Status.LifeBit )
   END_RUNG
   // the same network as SCL:
   #Status.LifeBit := #stPIData.Status.Life_Bit;
END_REGION

REGION Network 3: System Ready.
   RUNG wire#powerrail
      Contact( #stPIData.Status.SystemReady )
      Coil( #Status.SystemReady )
   END_RUNG
   // the same network as SCL:
   #Status.SystemReady := #stPIData.Status.SystemReady;
END_REGION

REGION Network 4: Error.
   RUNG wire#powerrail
      Contact( #stPIData.Status.Error )
      Coil( #Status.Error )
   END_RUNG
   // the same network as SCL:
   #Status.Error := #stPIData.Status.Error;
END_REGION

REGION Network 5: Fault word.
   RUNG wire#powerrail
      Move(in := #stPIData.Status.FaultCode, out1 => #tempFaultCode)
      Move(in := #tempFaultCodeOut, out1 => #Status.FaultCode)
   END_RUNG
   // the same network as SCL:
   #tempFaultCode := #stPIData.Status.FaultCode;
   #Status.FaultCode := #tempFaultCodeOut;
END_REGION

REGION Network 6: Products on the belt.
   RUNG wire#powerrail
      Move(in := #stPIData.Status.ProductsOnBelt, out1 => #Status.ProductsOnBelt)
   END_RUNG
   // the same network as SCL:
   #Status.ProductsOnBelt := #stPIData.Status.ProductsOnBelt;
END_REGION

REGION Network 7: Troughput.
   RUNG wire#powerrail
      Move(in := #stPIData.Status.Throughput, out1 => #Status.Throughput)
   END_RUNG
   // the same network as SCL:
   #Status.Throughput := #stPIData.Status.Throughput;
END_REGION

REGION Network 8: Belt speed.
   RUNG wire#powerrail
      Move(in := #stPIData.Status.BeltSpeed, out1 => #Status.BeltSpeed)
   END_RUNG
   // the same network as SCL:
   #Status.BeltSpeed := #stPIData.Status.BeltSpeed;
END_REGION

REGION Network 9: Belt acceleration.
   RUNG wire#powerrail
      Move(in := #stPIData.Status.BeltAcceleration, out1 => #Status.BeltAcceleration)
   END_RUNG
   // the same network as SCL:
   #Status.BeltAcceleration := #stPIData.Status.BeltAcceleration;
END_REGION

REGION Network 10: IO status.
   RUNG wire#powerrail
      Move(in := #stPIData.Status."IO Status", out1 => #tempIOStatus)
      Move(in := #tempIOStatusOut, out1 => #Status.IOstatus)
   END_RUNG
   // the same network as SCL:
   #tempIOStatus := #stPIData.Status."IO Status";
   #Status.IOstatus := #tempIOStatusOut;
END_REGION

REGION Network 11: Up Time.
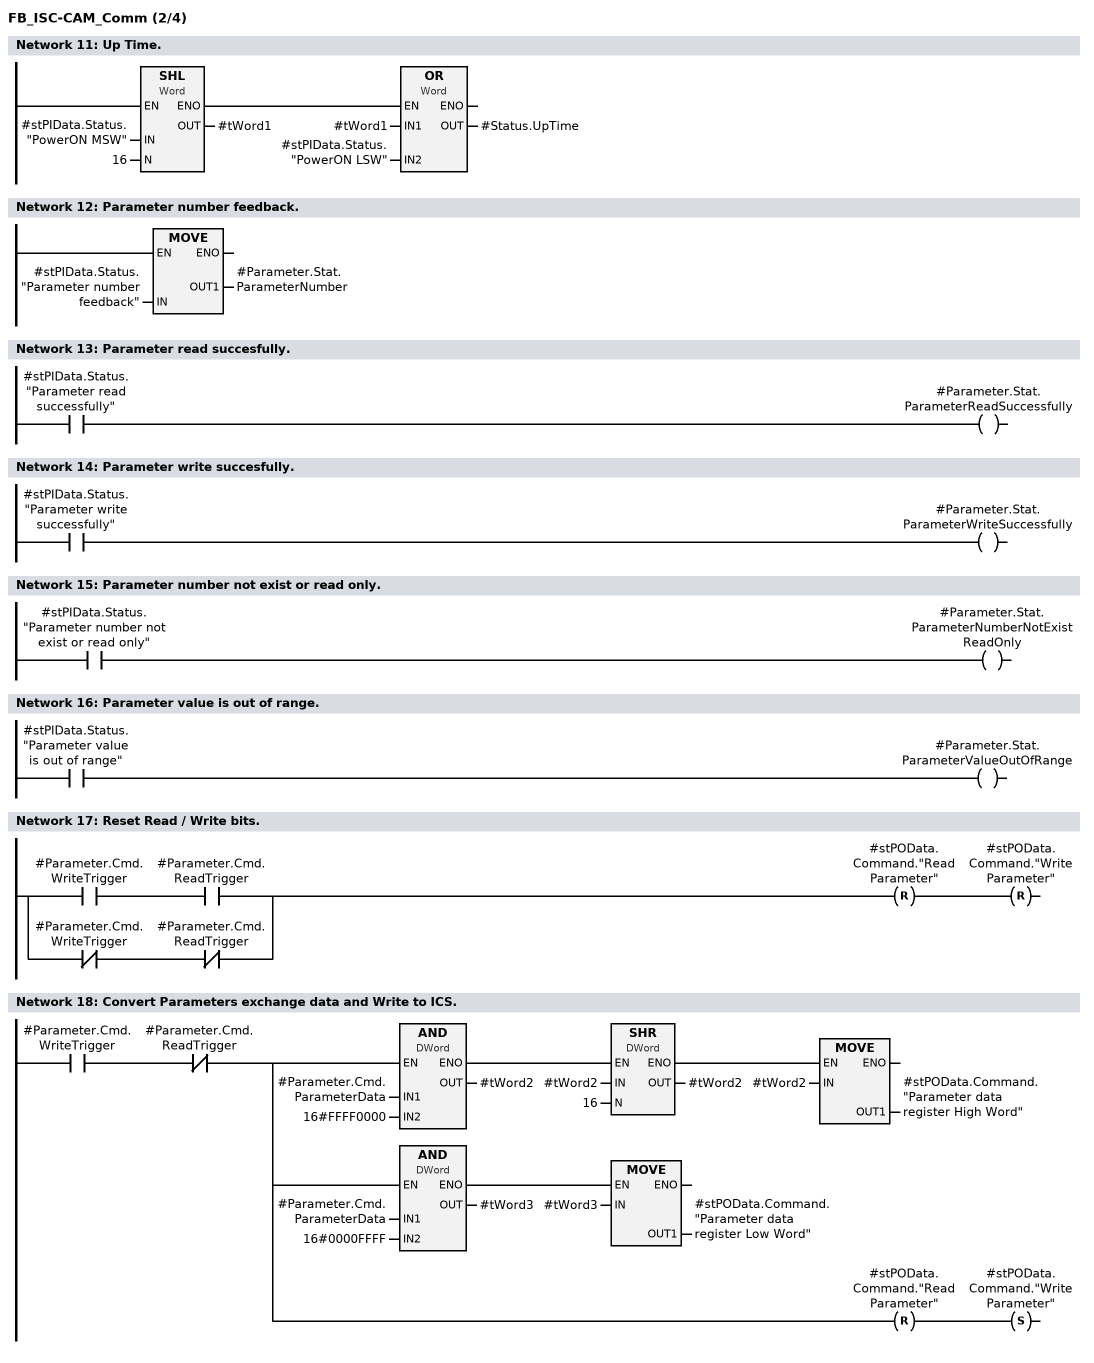
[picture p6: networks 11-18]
   #tWord1 := SHL(IN := #stPIData.Status."PowerON MSW", N := 16);
   #Status.UpTime := #tWord1 OR #stPIData.Status."PowerON LSW";
END_REGION

REGION Network 12: Parameter number feedback.
   RUNG wire#powerrail
      Move(in := #stPIData.Status."Parameter number feedback", out1 => #Parameter.Stat.ParameterNumber)
   END_RUNG
   // the same network as SCL:
   #Parameter.Stat.ParameterNumber := #stPIData.Status."Parameter number feedback";
END_REGION

REGION Network 13: Parameter read succesfully.
   RUNG wire#powerrail
      Contact( #stPIData.Status."Parameter read successfully" )
      Coil( #Parameter.Stat.ParameterReadSuccessfully )
   END_RUNG
   // the same network as SCL:
   #Parameter.Stat.ParameterReadSuccessfully := #stPIData.Status."Parameter read successfully";
END_REGION

REGION Network 14: Parameter write succesfully.
   RUNG wire#powerrail
      Contact( #stPIData.Status."Parameter write successfully" )
      Coil( #Parameter.Stat.ParameterWriteSuccessfully )
   END_RUNG
   // the same network as SCL:
   #Parameter.Stat.ParameterWriteSuccessfully := #stPIData.Status."Parameter write successfully";
END_REGION

REGION Network 15: Parameter number not exist or read only.
   RUNG wire#powerrail
      Contact( #stPIData.Status."Parameter number not exist or read only" )
      Coil( #Parameter.Stat.ParameterNumberNotExistReadOnly )
   END_RUNG
   // the same network as SCL:
   #Parameter.Stat.ParameterNumberNotExistReadOnly := #stPIData.Status."Parameter number not exist or read only";
END_REGION

REGION Network 16: Parameter value is out of range.
   RUNG wire#powerrail
      Contact( #stPIData.Status."Parameter value is out of range" )
      Coil( #Parameter.Stat.ParameterValueOutOfRange )
   END_RUNG
   // the same network as SCL:
   #Parameter.Stat.ParameterValueOutOfRange := #stPIData.Status."Parameter value is out of range";
END_REGION

REGION Network 17: Reset Read / Write bits.
   RUNG wire#powerrail
      Contact( #Parameter.Cmd.WriteTrigger )
      Contact( #Parameter.Cmd.ReadTrigger )
      wire#w1
      R_Coil( #stPOData.Command."Read Parameter" )
      R_Coil( #stPOData.Command."Write Parameter" )
   END_RUNG
   RUNG wire#powerrail
      I_Contact( #Parameter.Cmd.WriteTrigger )
      I_Contact( #Parameter.Cmd.ReadTrigger )
   END_RUNG wire#w1
   // the same network as SCL:
   IF (#Parameter.Cmd.WriteTrigger AND #Parameter.Cmd.ReadTrigger) OR (NOT #Parameter.Cmd.WriteTrigger AND NOT #Parameter.Cmd.ReadTrigger) THEN
       #stPOData.Command."Read Parameter" := FALSE;
       #stPOData.Command."Write Parameter" := FALSE;
   END_IF;
END_REGION

REGION Network 18: Convert Parameters exchange data and Write to ICS.
   RUNG wire#powerrail
      Contact( #Parameter.Cmd.WriteTrigger )
      I_Contact( #Parameter.Cmd.ReadTrigger )
      wire#w1
      { S7_Templates := "SrcType := DWord" } And(in1 := #Parameter.Cmd.ParameterData, in2 := 16#FFFF0000, out => #tWord2)
      { S7_Templates := "SrcType := DWord" } Shr(in := #tWord2, n := 16, out => #tWord2)
      Move(in := #tWord2, out1 => #stPOData.Command."Parameter data register High Word")
   END_RUNG
   RUNG wire#w1
      { S7_Templates := "SrcType := DWord" } And(in1 := #Parameter.Cmd.ParameterData, in2 := 16#0000FFFF, out => #tWord3)
      Move(in := #tWord3, out1 => #stPOData.Command."Parameter data register Low Word")
   END_RUNG
   RUNG wire#w1
      R_Coil( #stPOData.Command."Read Parameter" )
      S_Coil( #stPOData.Command."Write Parameter" )
   END_RUNG
   // the same network as SCL:
   IF #Parameter.Cmd.WriteTrigger AND NOT #Parameter.Cmd.ReadTrigger THEN
       #tWord2 := #Parameter.Cmd.ParameterData AND 16#FFFF0000;
       #tWord2 := SHR(IN := #tWord2, N := 16);
       #stPOData.Command."Parameter data register High Word" := #tWord2;
       #tWord3 := #Parameter.Cmd.ParameterData AND 16#0000FFFF;
       #stPOData.Command."Parameter data register Low Word" := #tWord3;
       #stPOData.Command."Read Parameter" := FALSE;
       #stPOData.Command."Write Parameter" := TRUE;
   END_IF;
END_REGION

REGION Network 19: Read parameters from ICS and Convert it into a DINT.
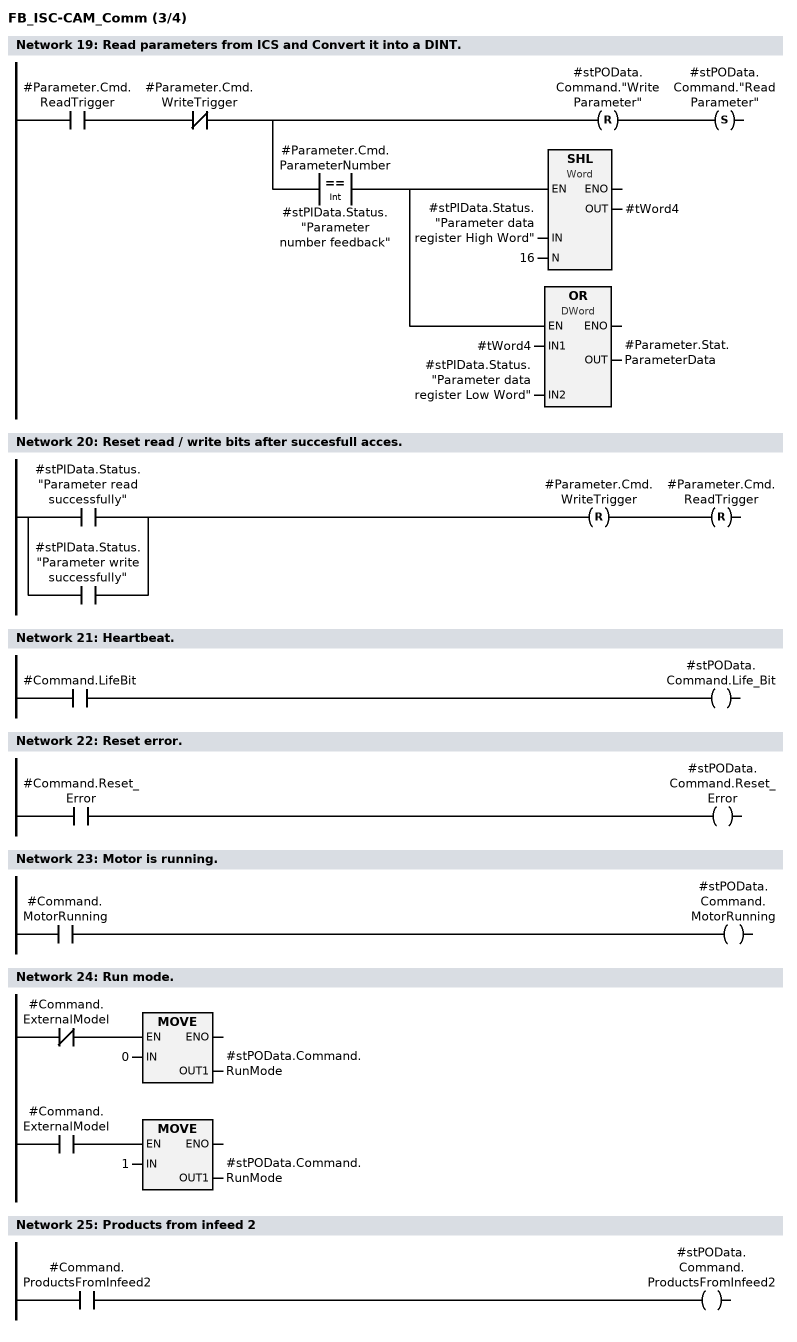
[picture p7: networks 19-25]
   #_w1 := #Parameter.Cmd.ReadTrigger AND NOT #Parameter.Cmd.WriteTrigger;
   IF #_w1 THEN
       #stPOData.Command."Write Parameter" := FALSE;
       #stPOData.Command."Read Parameter" := TRUE;
   END_IF;
   IF #_w1 AND (#Parameter.Cmd.ParameterNumber = #stPIData.Status."Parameter number feedback") THEN
       #tWord4 := SHL(IN := #stPIData.Status."Parameter data register High Word", N := 16);
       #Parameter.Stat.ParameterData := #tWord4 OR #stPIData.Status."Parameter data register Low Word";
   END_IF;
END_REGION

REGION Network 20: Reset read / write bits after succesfull acces.
   RUNG wire#powerrail
      Contact( #stPIData.Status."Parameter read successfully" )
      wire#w1
      R_Coil( #Parameter.Cmd.WriteTrigger )
      R_Coil( #Parameter.Cmd.ReadTrigger )
   END_RUNG
   RUNG wire#powerrail
      Contact( #stPIData.Status."Parameter write successfully" )
   END_RUNG wire#w1
   // the same network as SCL:
   IF #stPIData.Status."Parameter read successfully" OR #stPIData.Status."Parameter write successfully" THEN
       #Parameter.Cmd.WriteTrigger := FALSE;
       #Parameter.Cmd.ReadTrigger := FALSE;
   END_IF;
END_REGION

REGION Network 21: Heartbeat.
   RUNG wire#powerrail
      Contact( #Command.LifeBit )
      Coil( #stPOData.Command.Life_Bit )
   END_RUNG
   // the same network as SCL:
   #stPOData.Command.Life_Bit := #Command.LifeBit;
END_REGION

REGION Network 22: Reset error.
   RUNG wire#powerrail
      Contact( #Command.Reset_Error )
      Coil( #stPOData.Command.Reset_Error )
   END_RUNG
   // the same network as SCL:
   #stPOData.Command.Reset_Error := #Command.Reset_Error;
END_REGION

REGION Network 23: Motor is running.
   RUNG wire#powerrail
      Contact( #Command.MotorRunning )
      Coil( #stPOData.Command.MotorRunning )
   END_RUNG
   // the same network as SCL:
   #stPOData.Command.MotorRunning := #Command.MotorRunning;
END_REGION

REGION Network 24: Run mode.
   RUNG wire#powerrail
      I_Contact( #Command.ExternalModel )
      Move(in := 0, out1 => #stPOData.Command.RunMode)
   END_RUNG
   RUNG wire#powerrail
      Contact( #Command.ExternalModel )
      Move(in := 1, out1 => #stPOData.Command.RunMode)
   END_RUNG
   // the same network as SCL:
   IF NOT #Command.ExternalModel THEN #stPOData.Command.RunMode := 0; END_IF;
   IF #Command.ExternalModel THEN #stPOData.Command.RunMode := 1; END_IF;
END_REGION

REGION Network 25: Products from infeed 2
   RUNG wire#powerrail
      Contact( #Command.ProductsFromInfeed2 )
      Coil( #stPOData.Command.ProductsFromInfeed2 )
   END_RUNG
   // the same network as SCL:
   #stPOData.Command.ProductsFromInfeed2 := #Command.ProductsFromInfeed2;
END_REGION

REGION Network 26: Destination exit 1 enable.
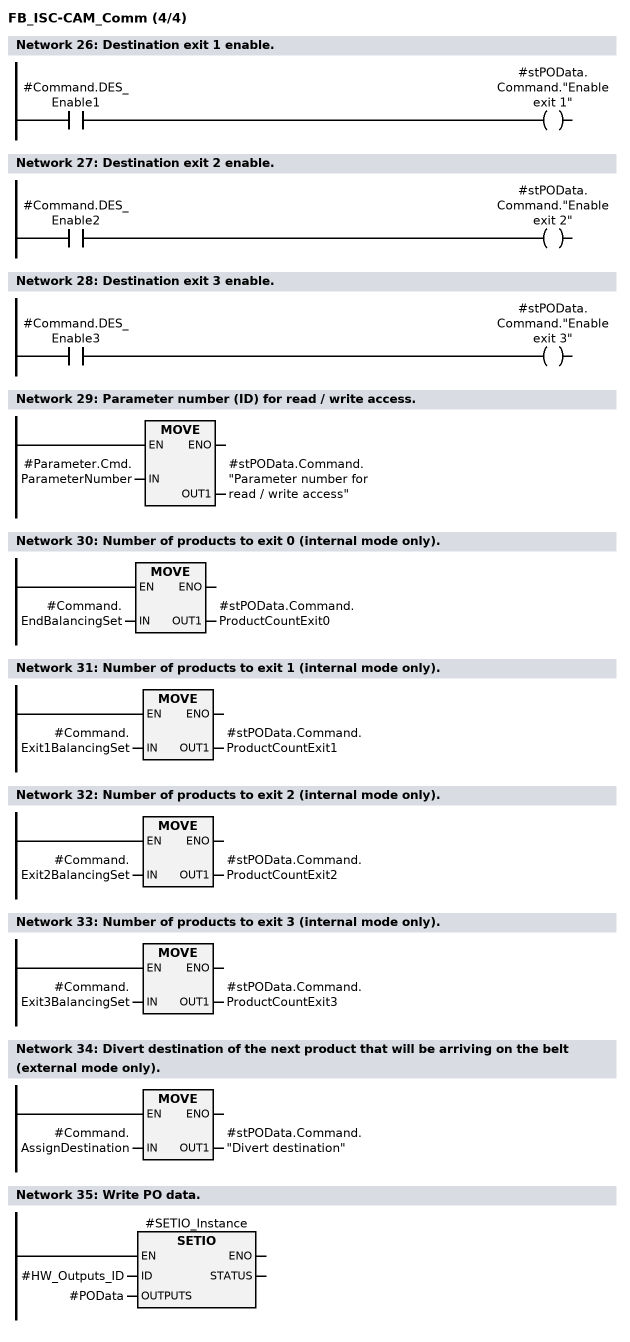
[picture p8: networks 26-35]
   RUNG wire#powerrail
      Contact( #Command.DES_Enable1 )
      Coil( #stPOData.Command."Enable exit 1" )
   END_RUNG
   // the same network as SCL:
   #stPOData.Command."Enable exit 1" := #Command.DES_Enable1;
END_REGION

REGION Network 27: Destination exit 2 enable.
   RUNG wire#powerrail
      Contact( #Command.DES_Enable2 )
      Coil( #stPOData.Command."Enable exit 2" )
   END_RUNG
   // the same network as SCL:
   #stPOData.Command."Enable exit 2" := #Command.DES_Enable2;
END_REGION

REGION Network 28: Destination exit 3 enable.
   RUNG wire#powerrail
      Contact( #Command.DES_Enable3 )
      Coil( #stPOData.Command."Enable exit 3" )
   END_RUNG
   // the same network as SCL:
   #stPOData.Command."Enable exit 3" := #Command.DES_Enable3;
END_REGION

REGION Network 29: Parameter number (ID) for read / write access.
   RUNG wire#powerrail
      Move(in := #Parameter.Cmd.ParameterNumber, out1 => #stPOData.Command."Parameter number for read / write access")
   END_RUNG
   // the same network as SCL:
   #stPOData.Command."Parameter number for read / write access" := #Parameter.Cmd.ParameterNumber;
END_REGION

REGION Network 30: Number of products to exit 0 (internal mode only).
   RUNG wire#powerrail
      Move(in := #Command.EndBalancingSet, out1 => #stPOData.Command.ProductCountExit0)
   END_RUNG
   // the same network as SCL:
   #stPOData.Command.ProductCountExit0 := #Command.EndBalancingSet;
END_REGION

REGION Network 31: Number of products to exit 1 (internal mode only).
   RUNG wire#powerrail
      Move(in := #Command.Exit1BalancingSet, out1 => #stPOData.Command.ProductCountExit1)
   END_RUNG
   // the same network as SCL:
   #stPOData.Command.ProductCountExit1 := #Command.Exit1BalancingSet;
END_REGION

REGION Network 32: Number of products to exit 2 (internal mode only).
   RUNG wire#powerrail
      Move(in := #Command.Exit2BalancingSet, out1 => #stPOData.Command.ProductCountExit2)
   END_RUNG
   // the same network as SCL:
   #stPOData.Command.ProductCountExit2 := #Command.Exit2BalancingSet;
END_REGION

REGION Network 33: Number of products to exit 3 (internal mode only).
   RUNG wire#powerrail
      Move(in := #Command.Exit3BalancingSet, out1 => #stPOData.Command.ProductCountExit3)
   END_RUNG
   // the same network as SCL:
   #stPOData.Command.ProductCountExit3 := #Command.Exit3BalancingSet;
END_REGION

REGION Network 34: Divert destination of the next product that will be arriving on the belt (external mode only).
   RUNG wire#powerrail
      Move(in := #Command.AssignDestination, out1 => #stPOData.Command."Divert destination")
   END_RUNG
   // the same network as SCL:
   #stPOData.Command."Divert destination" := #Command.AssignDestination;
END_REGION

REGION Network 35: Write PO data.
   #SETIO_Instance(ID := #HW_Outputs_ID, OUTPUTS := #POData);   // SETIO
END_REGION

REGION Network 36 (SCL): Temporarly data collection.

   #DataCollection.BeltRunTime := DWORD_TO_DINT(SHL(IN := WORD_TO_DWORD(#stPIData.DataCollection1.BeltRunTime_MSW), N := 16) OR #stPIData.DataCollection1.BeltRunTime_LSW);
   #DataCollection.BeltTravelDistance := DWORD_TO_DINT(SHL(IN := WORD_TO_DWORD(#stPIData.DataCollection1.BeltTravelDistance_MSW), N := 16) OR #stPIData.DataCollection1.BeltTravelDistance_LSW);
   #DataCollection."ActivationCount Zone0" := DWORD_TO_DINT(SHL(IN := WORD_TO_DWORD(#stPIData.DataCollection1.ActivationCount_Zone0_MSW), N := 16) OR #stPIData.DataCollection1.ActivationCount_Zone0_LSW);
   #DataCollection."ActivationCount Zone1" := DWORD_TO_DINT(SHL(IN := WORD_TO_DWORD(#stPIData.DataCollection1.ActivationCount_Zone1_MSW), N := 16) OR #stPIData.DataCollection1.ActivationCount_Zone1_LSW);
   #DataCollection."ActivationCount Zone2" := DWORD_TO_DINT(SHL(IN := WORD_TO_DWORD(#stPIData.DataCollection1.ActivationCount_Zone2_MSW), N := 16) OR #stPIData.DataCollection1.ActivationCount_Zone2_LSW);
   #DataCollection.ProductCount := DWORD_TO_DINT(SHL(IN := WORD_TO_DWORD(#stPIData.DataCollection1.ProductCount_MSW), N := 16) OR #stPIData.DataCollection1.ProductCount_LSW);
   #DataCollection.StartStops := DWORD_TO_DINT(SHL(IN := WORD_TO_DWORD(#stPIData.DataCollection1.StartStops_MSW), N := 16) OR #stPIData.DataCollection1.StartStops_LSW);
   #DataCollection.GapToSmallCount := DWORD_TO_DINT(SHL(IN := WORD_TO_DWORD(#stPIData.DataCollection1.GapToSmallCount_MSW), N := 16) OR #stPIData.DataCollection1.GapToSmallCount_LSW);
   #DataCollection.FaultCount := WORD_TO_INT(#stPIData.DataCollection2.FaultCount);
   #DataCollection.MaxBeltSpeed := WORD_TO_INT(#stPIData.DataCollection2.MaxBeltSpeed);
   #DataCollection.PeakAcceleration := WORD_TO_INT(#stPIData.DataCollection2.PeakAcceleration);
   #DataCollection.PeakDecceleration := WORD_TO_INT(#stPIData.DataCollection2.PeakDecceleration);
END_REGION
END_FUNCTION_BLOCK

// folder: 000-099_General/Maintenance

FUNCTION_BLOCK "FB_ISC-CAM_Maintenance"   // FB8, SCL
{ S7_Optimized_Access := 'TRUE' }
VERSION : 0.1
   VAR_INPUT
      "Counter" : DInt;
      Threshold : DInt;
   END_VAR
   VAR_OUTPUT
      CountUnitlNextMaintenance : DInt;
   END_VAR
   VAR_IN_OUT
      Maintenance : Bool;
   END_VAR
   VAR
      MaintenanceCounter : DInt;
      LastCounter : DInt;
   END_VAR
BEGIN

   IF #Threshold > 0 THEN
       IF (#Counter - #LastCounter)>#Threshold THEN
           #LastCounter := #Counter;
           #Maintenance := true;
       END_IF;
       #CountUnitlNextMaintenance := #Threshold - (#Counter - #LastCounter);
   ELSE
       #Maintenance := false;
       #LastCounter := 0; // doubbles as a way to reset the internal Maintenance counter.
       #CountUnitlNextMaintenance := 0;
   END_IF;
END_FUNCTION_BLOCK

// folder: 000-099_General/Simulation

FUNCTION_BLOCK "PhotoEye"   // FB5, SCL
{ S7_Optimized_Access := 'TRUE' }
VERSION : 0.1
   VAR_INPUT
      EncTime : Time;
   END_VAR
   VAR_OUTPUT
      EncOut : Bool;
   END_VAR
   VAR
      EncTime_0 : TON_TIME;
      EncTime_1 : TON_TIME;
      EncB2ndS : Bool;
      Enc : DInt;
   END_VAR
BEGIN
   // Encoder.
   // #EncTime := t#5ms;
   #EncTime_0(IN := NOT #EncTime_1.Q,
              PT := #EncTime);

   #EncTime_1(IN := #EncTime_0.Q,
              PT := #EncTime);

   IF #EncTime_0.Q AND NOT #EncB2ndS THEN
       #EncB2ndS := true;
       #Enc := #Enc + 1;
   END_IF;

   IF NOT #EncTime_0.Q AND #EncB2ndS THEN
       #EncB2ndS := false;
   END_IF;

   #EncOut := DINT_TO_BOOL(#Enc);
   // "Sim_EncoderOutput(1)" := #EncOut;
END_FUNCTION_BLOCK

FUNCTION_BLOCK "Encoder"   // FB6, SCL
{ S7_Optimized_Access := 'TRUE' }
VERSION : 0.1
   VAR_INPUT
      EncTime : Time;
   END_VAR
   VAR_OUTPUT
      PeOut : Bool;
   END_VAR
   VAR
      EncTime_0 : TON_TIME;
      EncTime_1 : TON_TIME;
   END_VAR
BEGIN
   // PhotoEye.
   #EncTime_0(IN := NOT #EncTime_1.Q,
              PT := #EncTime);

   #EncTime_1(IN := #EncTime_0.Q,
              PT := #EncTime);

   #PeOut := #EncTime_0.Q;
END_FUNCTION_BLOCK

// folder: 100-199_Machine_001

FUNCTION_BLOCK "M001_Faults"   // FB16, LAD
TITLE = Machine faults
{ S7_Optimized_Access := 'FALSE' }
VERSION : 0.1
   VAR
      sBool : Bool;
      FG0_Timer_00 : TON_TIME;
      FG0_Timer_01 : TON_TIME;
      Faultbits : "dt_ISCCAM_Alarms";
      faultCount AT Faultbits : DInt;
   END_VAR
BEGIN

REGION Network 1 (SCL): Faults
   //Fault group 0, ISC device state errors.
   //Group reset
   IF ("DB_General_HMI".GeneralResetBtnCmd) THEN
       "DB_M001_HMI".FaultBits.CommsAlarm := 0;
       "DB_M001_HMI".FaultBits.Fault0Alarm := 0;
       "DB_M001_HMI".FaultBits.Fault1Alarm := 0;
       "DB_M001_HMI".FaultBits.Fault2Alarm := 0;
       "DB_M001_HMI".FaultBits.Fault3Alarm := 0;
       "DB_M001_HMI".FaultBits.Fault4Alarm := 0;
       "DB_M001_HMI".FaultBits.Fault5Alarm := 0;
       "DB_M001_HMI".FaultBits.Fault6Alarm := 0;
       "DB_M001_HMI".FaultBits.Fault7Alarm := 0;
       "DB_M001_HMI".FaultBits.Fault8Alarm := 0;
       "DB_M001_HMI".FaultBits.Fault9Alarm := 0;
       "DB_M001_HMI".FaultBits.Fault10Alarm := 0;
       "DB_M001_HMI".FaultBits.Fault11Alarm := 0;
       "DB_M001_HMI".FaultBits.Fault12Alarm := 0;
       "DB_M001_HMI".FaultBits.Fault13Alarm := 0;
       "DB_M001_HMI".FaultBits.Fault14Alarm := 0;
       "DB_M001_HMI".FaultBits.Fault15Alarm := 0;
   END_IF;


   //Lifebit error
   #FG0_Timer_00(IN := NOT "DB_M001_Status"."ISC-CAM".Status.LifeBit,
                 PT := T#3s);
   #FG0_Timer_01(IN := "DB_M001_Status"."ISC-CAM".Status.LifeBit,
                 PT := T#3s);


   IF (NOT "DB_M001_HMI".FaultBits.CommsAlarm AND (#FG0_Timer_00.Q OR #FG0_Timer_01.Q)) THEN
       "DB_M001_HMI".FaultBits.CommsAlarm := 1;
   END_IF;

   IF (NOT "DB_M001_HMI".FaultBits.Fault0Alarm AND NOT "DB_M001_Status"."ISC-CAM".Status.FaultCode."FaultCode.0") THEN
       "DB_M001_HMI".FaultBits.Fault0Alarm := 1;
   END_IF;

   IF (NOT "DB_M001_HMI".FaultBits.Fault1Alarm AND NOT "DB_M001_Status"."ISC-CAM".Status.FaultCode."FaultCode.1") THEN
       "DB_M001_HMI".FaultBits.Fault1Alarm := 1;
   END_IF;

   IF (NOT "DB_M001_HMI".FaultBits.Fault2Alarm AND NOT "DB_M001_Status"."ISC-CAM".Status.FaultCode."FaultCode.2") THEN
       "DB_M001_HMI".FaultBits.Fault2Alarm := 1;
   END_IF;

   IF (NOT "DB_M001_HMI".FaultBits.Fault3Alarm AND NOT "DB_M001_Status"."ISC-CAM".Status.FaultCode."FaultCode.3") THEN
       "DB_M001_HMI".FaultBits.Fault3Alarm := 1;
   END_IF;

   IF (NOT "DB_M001_HMI".FaultBits.Fault4Alarm AND NOT "DB_M001_Status"."ISC-CAM".Status.FaultCode."FaultCode.4") THEN
       "DB_M001_HMI".FaultBits.Fault4Alarm := 1;
   END_IF;

   IF (NOT "DB_M001_HMI".FaultBits.Fault5Alarm AND NOT "DB_M001_Status"."ISC-CAM".Status.FaultCode."FaultCode.5") THEN
       "DB_M001_HMI".FaultBits.Fault5Alarm := 1;
   END_IF;

   IF (NOT "DB_M001_HMI".FaultBits.Fault6Alarm AND NOT "DB_M001_Status"."ISC-CAM".Status.FaultCode."FaultCode.6") THEN
       "DB_M001_HMI".FaultBits.Fault6Alarm := 1;
   END_IF;

   IF (NOT "DB_M001_HMI".FaultBits.Fault7Alarm AND NOT "DB_M001_Status"."ISC-CAM".Status.FaultCode."FaultCode.7") THEN
       "DB_M001_HMI".FaultBits.Fault7Alarm := 1;
   END_IF;

   IF (NOT "DB_M001_HMI".FaultBits.Fault8Alarm AND NOT "DB_M001_Status"."ISC-CAM".Status.FaultCode."FaultCode.8") THEN
       "DB_M001_HMI".FaultBits.Fault8Alarm := 1;
   END_IF;

   IF (NOT "DB_M001_HMI".FaultBits.Fault9Alarm AND NOT "DB_M001_Status"."ISC-CAM".Status.FaultCode."FaultCode.9") THEN
       "DB_M001_HMI".FaultBits.Fault9Alarm := 1;
   END_IF;

   IF (NOT "DB_M001_HMI".FaultBits.Fault10Alarm AND NOT "DB_M001_Status"."ISC-CAM".Status.FaultCode."FaultCode.10") THEN
       "DB_M001_HMI".FaultBits.Fault10Alarm := 1;
   END_IF;

   IF (NOT "DB_M001_HMI".FaultBits.Fault11Alarm AND NOT "DB_M001_Status"."ISC-CAM".Status.FaultCode."FaultCode.11") THEN
       "DB_M001_HMI".FaultBits.Fault11Alarm := 1;
   END_IF;

   IF (NOT "DB_M001_HMI".FaultBits.Fault12Alarm AND NOT "DB_M001_Status"."ISC-CAM".Status.FaultCode."FaultCode.12") THEN
       "DB_M001_HMI".FaultBits.Fault12Alarm := 1;
   END_IF;

   IF (NOT "DB_M001_HMI".FaultBits.Fault13Alarm AND NOT "DB_M001_Status"."ISC-CAM".Status.FaultCode."FaultCode.13") THEN
       "DB_M001_HMI".FaultBits.Fault13Alarm := 1;
   END_IF;

   IF (NOT "DB_M001_HMI".FaultBits.Fault14Alarm AND NOT "DB_M001_Status"."ISC-CAM".Status.FaultCode."FaultCode.14") THEN
       "DB_M001_HMI".FaultBits.Fault14Alarm := 1;
   END_IF;

   IF (NOT "DB_M001_HMI".FaultBits.Fault15Alarm AND NOT "DB_M001_Status"."ISC-CAM".Status.FaultCode."FaultCode.15") THEN
       "DB_M001_HMI".FaultBits.Fault15Alarm := 1;
   END_IF;

   //Fault count
   #Faultbits := "DB_M001_HMI".FaultBits;

   IF (#faultCount > 0 AND NOT "DB_M001_HMI".Fault) THEN
       "DB_M001_HMI".Fault := 1;
   ELSIF #faultCount = 0 AND "DB_M001_HMI".Fault THEN
       "DB_M001_HMI".Fault := 0;
   END_IF;
END_REGION
END_FUNCTION_BLOCK

FUNCTION_BLOCK "M001_Main"   // FB18, LAD
TITLE = Main Machine routine.
{ S7_Optimized_Access := 'TRUE' }
VERSION : 0.1
   VAR
      Faults : "M001_Faults";
      Maintenance : "M001_Maintenance";
      EncSim : "Encoder";
      PE : "PhotoEye";
      "ISC-CAM_Comm" : "FB_ISC-CAM_Comm";
      Diagonistics : DIS;
      RET_VAL : Int;
      CNT_DIAG : UInt;
   END_VAR
BEGIN

REGION Network 1: Communication status
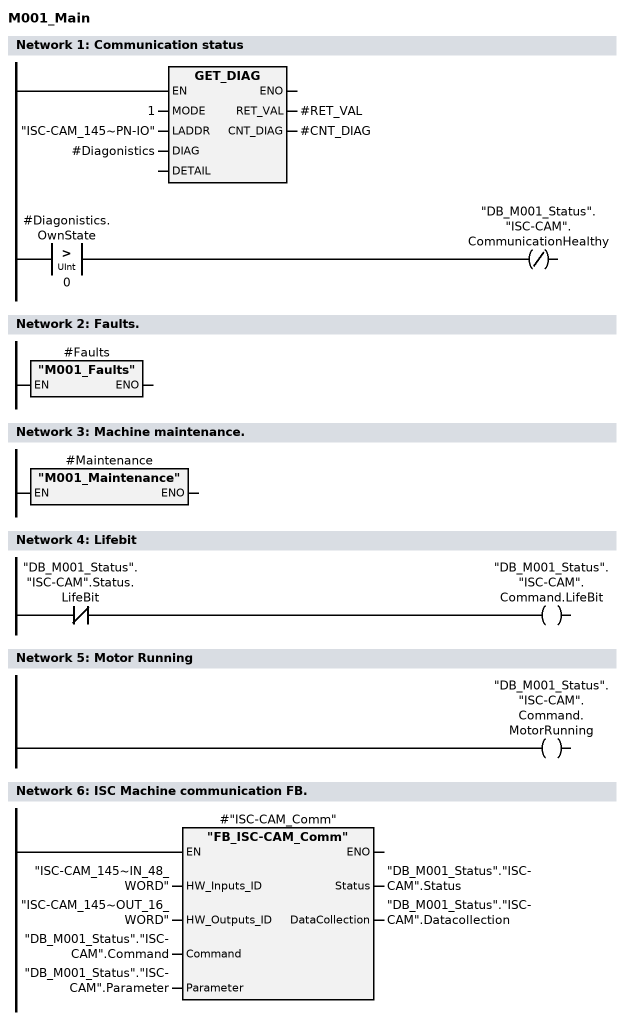
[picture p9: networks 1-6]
   #RET_VAL := GET_DIAG(MODE := 1, LADDR := "ISC-CAM_145~PN-IO", DIAG := #Diagonistics, CNT_DIAG => #CNT_DIAG);
   "DB_M001_Status"."ISC-CAM".CommunicationHealthy := NOT (#Diagonistics.OwnState > 0);
END_REGION

REGION Network 2: Faults.
   RUNG wire#powerrail
      #Faults()
   END_RUNG
   // the same network as SCL:
   #Faults();   // "M001_Faults"
END_REGION

REGION Network 3: Machine maintenance.
   RUNG wire#powerrail
      #Maintenance()
   END_RUNG
   // the same network as SCL:
   #Maintenance();   // "M001_Maintenance"
END_REGION

REGION Network 4: Lifebit
   RUNG wire#powerrail
      I_Contact( "DB_M001_Status"."ISC-CAM".Status.LifeBit )
      Coil( "DB_M001_Status"."ISC-CAM".Command.LifeBit )
   END_RUNG
   // the same network as SCL:
   "DB_M001_Status"."ISC-CAM".Command.LifeBit := NOT "DB_M001_Status"."ISC-CAM".Status.LifeBit;
END_REGION

REGION Network 5: Motor Running
   RUNG wire#powerrail
      Coil( "DB_M001_Status"."ISC-CAM".Command.MotorRunning )
   END_RUNG
   // the same network as SCL:
   "DB_M001_Status"."ISC-CAM".Command.MotorRunning := TRUE;
END_REGION

REGION Network 6: ISC Machine communication FB.
   RUNG wire#powerrail
      #"ISC-CAM_Comm"(HW_Inputs_ID := "ISC-CAM_145~IN_48_WORD", HW_Outputs_ID := "ISC-CAM_145~OUT_16_WORD", Command := "DB_M001_Status"."ISC-CAM".Command, Parameter := "DB_M001_Status"."ISC-CAM".Parameter, Status => "DB_M001_Status"."ISC-CAM".Status, DataCollection => "DB_M001_Status"."ISC-CAM".Datacollection)
   END_RUNG
   // the same network as SCL:
   #"ISC-CAM_Comm"(HW_Inputs_ID := "ISC-CAM_145~IN_48_WORD",   // "FB_ISC-CAM_Comm"
                   HW_Outputs_ID := "ISC-CAM_145~OUT_16_WORD",
                   Command := "DB_M001_Status"."ISC-CAM".Command,
                   Parameter := "DB_M001_Status"."ISC-CAM".Parameter,
                   Status => "DB_M001_Status"."ISC-CAM".Status,
                   DataCollection => "DB_M001_Status"."ISC-CAM".Datacollection);
END_REGION
END_FUNCTION_BLOCK

FUNCTION_BLOCK "M001_Maintenance"   // FB19, LAD
TITLE = Machine maintenance.
{ S7_Optimized_Access := 'TRUE' }
VERSION : 0.1
   VAR
      Maintenance : Array[0..15] of "FB_ISC-CAM_Maintenance";
      Threshold : Array[0..15] of DInt;
   END_VAR
BEGIN

REGION Network 1: Simulation only.
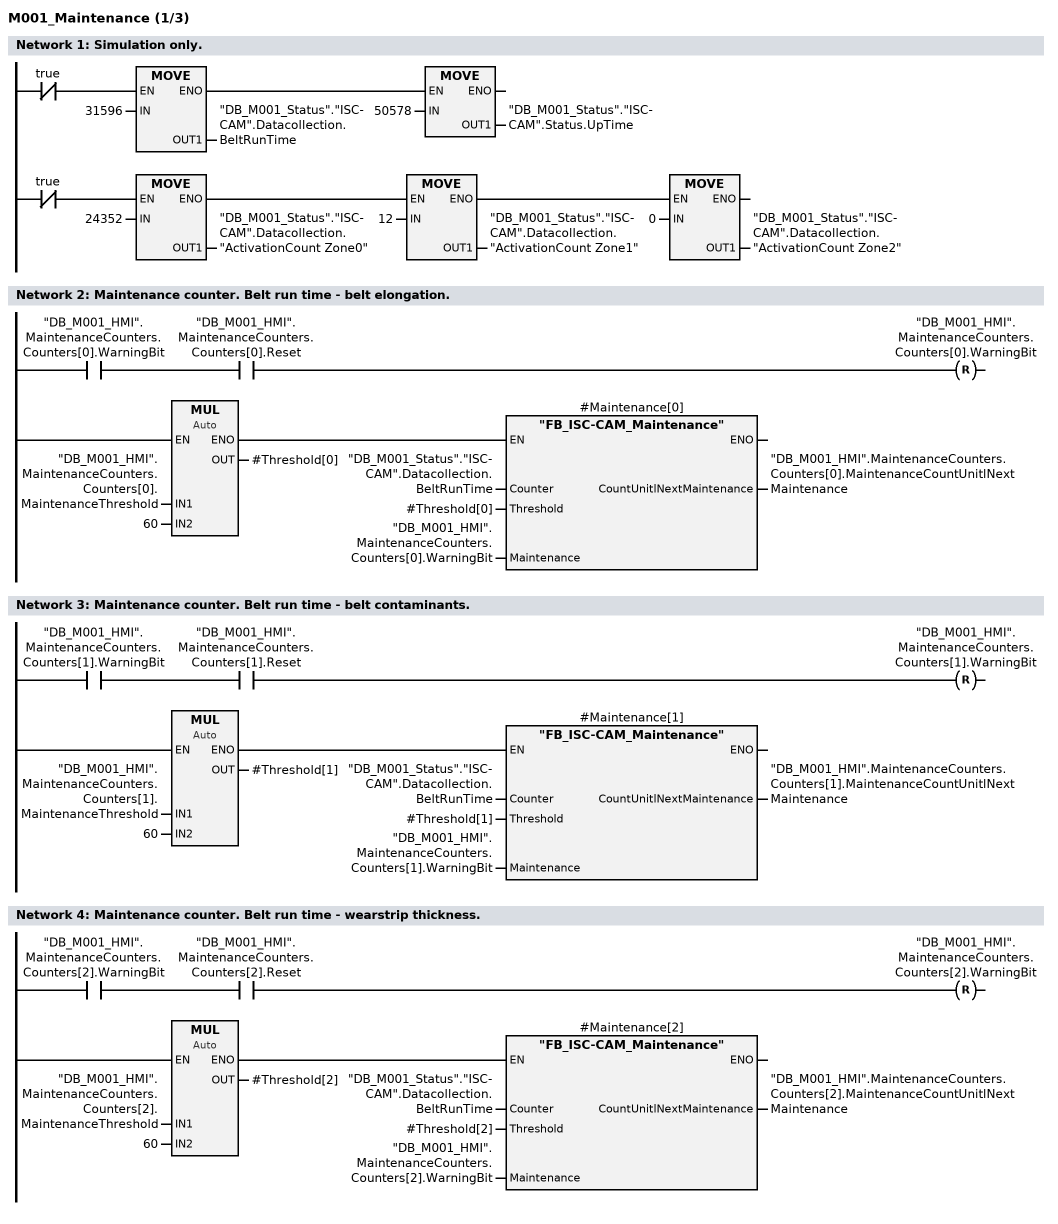
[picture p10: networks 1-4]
   RUNG wire#powerrail
      I_Contact( true )
      Move(in := 31596, out1 => "DB_M001_Status"."ISC-CAM".Datacollection.BeltRunTime)
      Move(in := 50578, out1 => "DB_M001_Status"."ISC-CAM".Status.UpTime)
   END_RUNG
   RUNG wire#powerrail
      I_Contact( true )
      Move(in := 24352, out1 => "DB_M001_Status"."ISC-CAM".Datacollection."ActivationCount Zone0")
      Move(in := 12, out1 => "DB_M001_Status"."ISC-CAM".Datacollection."ActivationCount Zone1")
      Move(in := 0, out1 => "DB_M001_Status"."ISC-CAM".Datacollection."ActivationCount Zone2")
   END_RUNG
   // the same network as SCL:
   IF NOT true THEN
       "DB_M001_Status"."ISC-CAM".Datacollection.BeltRunTime := 31596;
       "DB_M001_Status"."ISC-CAM".Status.UpTime := 50578;
       "DB_M001_Status"."ISC-CAM".Datacollection."ActivationCount Zone0" := 24352;
       "DB_M001_Status"."ISC-CAM".Datacollection."ActivationCount Zone1" := 12;
       "DB_M001_Status"."ISC-CAM".Datacollection."ActivationCount Zone2" := 0;
   END_IF;
END_REGION

REGION Network 2: Maintenance counter. Belt run time - belt elongation.
   RUNG wire#powerrail
      Contact( "DB_M001_HMI".MaintenanceCounters.Counters[0].WarningBit )
      Contact( "DB_M001_HMI".MaintenanceCounters.Counters[0].Reset )
      R_Coil( "DB_M001_HMI".MaintenanceCounters.Counters[0].WarningBit )
   END_RUNG
   RUNG wire#powerrail
      Mul(in1 := "DB_M001_HMI".MaintenanceCounters.Counters[0].MaintenanceThreshold, in2 := 60, out => #Threshold[0])
      #Maintenance[0]("Counter" := "DB_M001_Status"."ISC-CAM".Datacollection.BeltRunTime, Threshold := #Threshold[0], Maintenance := "DB_M001_HMI".MaintenanceCounters.Counters[0].WarningBit, CountUnitlNextMaintenance => "DB_M001_HMI".MaintenanceCounters.Counters[0].MaintenanceCountUnitlNextMaintenance)
   END_RUNG
   // the same network as SCL:
   IF "DB_M001_HMI".MaintenanceCounters.Counters[0].WarningBit AND "DB_M001_HMI".MaintenanceCounters.Counters[0].Reset THEN
       "DB_M001_HMI".MaintenanceCounters.Counters[0].WarningBit := FALSE;
   END_IF;
   #Threshold[0] := "DB_M001_HMI".MaintenanceCounters.Counters[0].MaintenanceThreshold * 60;
   #Maintenance[0]("Counter" := "DB_M001_Status"."ISC-CAM".Datacollection.BeltRunTime,   // "FB_ISC-CAM_Maintenance"
                   Threshold := #Threshold[0],
                   Maintenance := "DB_M001_HMI".MaintenanceCounters.Counters[0].WarningBit,
                   CountUnitlNextMaintenance => "DB_M001_HMI".MaintenanceCounters.Counters[0].MaintenanceCountUnitlNextMaintenance);
END_REGION

REGION Network 3: Maintenance counter. Belt run time - belt contaminants.
   RUNG wire#powerrail
      Contact( "DB_M001_HMI".MaintenanceCounters.Counters[1].WarningBit )
      Contact( "DB_M001_HMI".MaintenanceCounters.Counters[1].Reset )
      R_Coil( "DB_M001_HMI".MaintenanceCounters.Counters[1].WarningBit )
   END_RUNG
   RUNG wire#powerrail
      Mul(in1 := "DB_M001_HMI".MaintenanceCounters.Counters[1].MaintenanceThreshold, in2 := 60, out => #Threshold[1])
      #Maintenance[1]("Counter" := "DB_M001_Status"."ISC-CAM".Datacollection.BeltRunTime, Threshold := #Threshold[1], Maintenance := "DB_M001_HMI".MaintenanceCounters.Counters[1].WarningBit, CountUnitlNextMaintenance => "DB_M001_HMI".MaintenanceCounters.Counters[1].MaintenanceCountUnitlNextMaintenance)
   END_RUNG
   // the same network as SCL:
   IF "DB_M001_HMI".MaintenanceCounters.Counters[1].WarningBit AND "DB_M001_HMI".MaintenanceCounters.Counters[1].Reset THEN
       "DB_M001_HMI".MaintenanceCounters.Counters[1].WarningBit := FALSE;
   END_IF;
   #Threshold[1] := "DB_M001_HMI".MaintenanceCounters.Counters[1].MaintenanceThreshold * 60;
   #Maintenance[1]("Counter" := "DB_M001_Status"."ISC-CAM".Datacollection.BeltRunTime,   // "FB_ISC-CAM_Maintenance"
                   Threshold := #Threshold[1],
                   Maintenance := "DB_M001_HMI".MaintenanceCounters.Counters[1].WarningBit,
                   CountUnitlNextMaintenance => "DB_M001_HMI".MaintenanceCounters.Counters[1].MaintenanceCountUnitlNextMaintenance);
END_REGION

REGION Network 4: Maintenance counter. Belt run time - wearstrip thickness.
   RUNG wire#powerrail
      Contact( "DB_M001_HMI".MaintenanceCounters.Counters[2].WarningBit )
      Contact( "DB_M001_HMI".MaintenanceCounters.Counters[2].Reset )
      R_Coil( "DB_M001_HMI".MaintenanceCounters.Counters[2].WarningBit )
   END_RUNG
   RUNG wire#powerrail
      Mul(in1 := "DB_M001_HMI".MaintenanceCounters.Counters[2].MaintenanceThreshold, in2 := 60, out => #Threshold[2])
      #Maintenance[2]("Counter" := "DB_M001_Status"."ISC-CAM".Datacollection.BeltRunTime, Threshold := #Threshold[2], Maintenance := "DB_M001_HMI".MaintenanceCounters.Counters[2].WarningBit, CountUnitlNextMaintenance => "DB_M001_HMI".MaintenanceCounters.Counters[2].MaintenanceCountUnitlNextMaintenance)
   END_RUNG
   // the same network as SCL:
   IF "DB_M001_HMI".MaintenanceCounters.Counters[2].WarningBit AND "DB_M001_HMI".MaintenanceCounters.Counters[2].Reset THEN
       "DB_M001_HMI".MaintenanceCounters.Counters[2].WarningBit := FALSE;
   END_IF;
   #Threshold[2] := "DB_M001_HMI".MaintenanceCounters.Counters[2].MaintenanceThreshold * 60;
   #Maintenance[2]("Counter" := "DB_M001_Status"."ISC-CAM".Datacollection.BeltRunTime,   // "FB_ISC-CAM_Maintenance"
                   Threshold := #Threshold[2],
                   Maintenance := "DB_M001_HMI".MaintenanceCounters.Counters[2].WarningBit,
                   CountUnitlNextMaintenance => "DB_M001_HMI".MaintenanceCounters.Counters[2].MaintenanceCountUnitlNextMaintenance);
END_REGION

REGION Network 5: Maintenance counter. Belt run time - helix rollers.
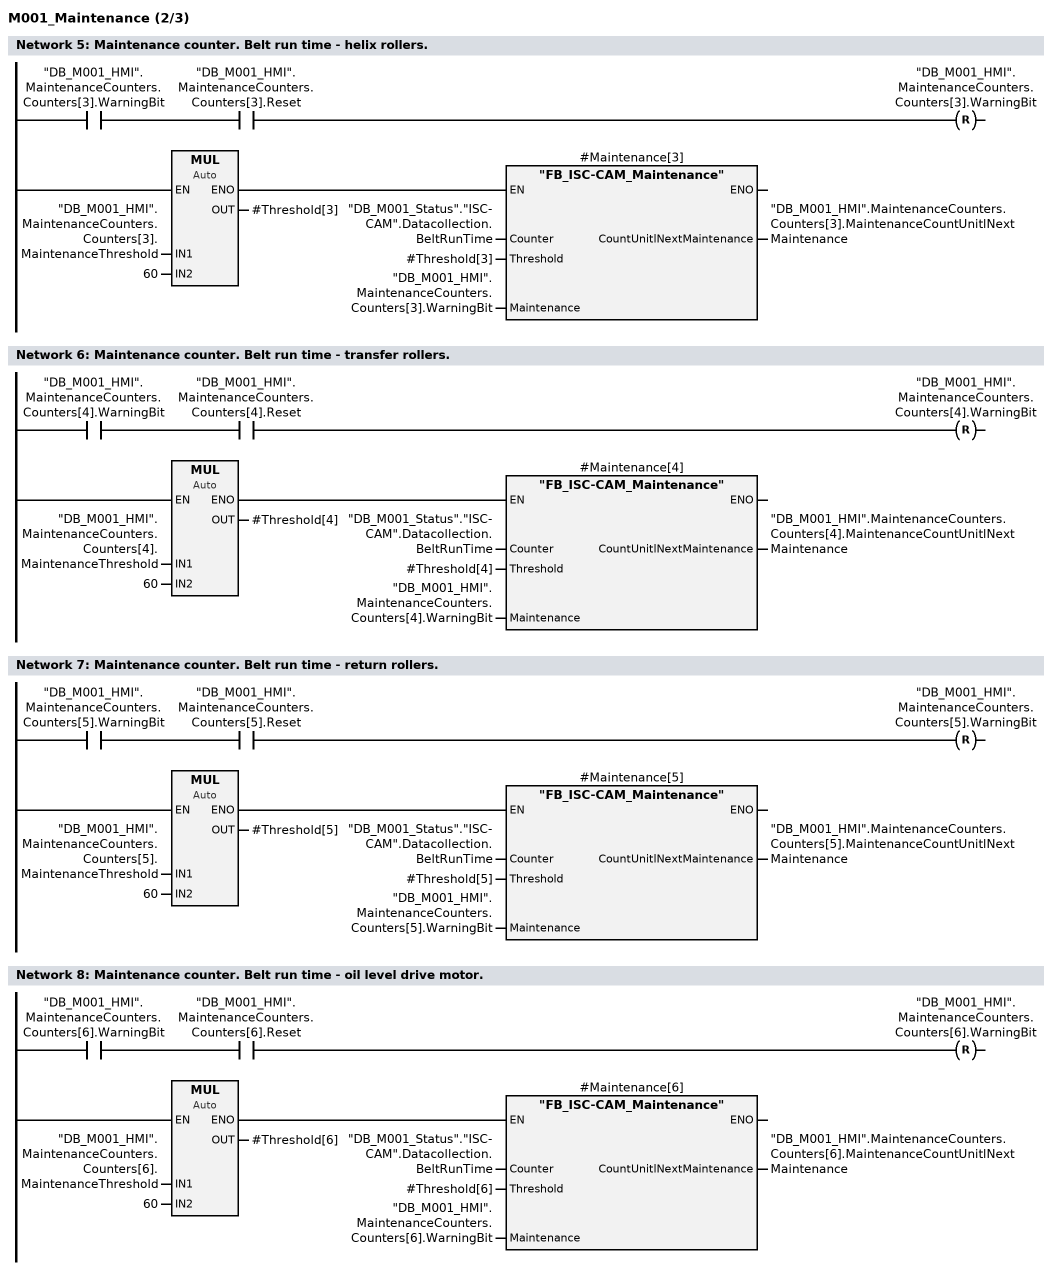
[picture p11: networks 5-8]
   RUNG wire#powerrail
      Contact( "DB_M001_HMI".MaintenanceCounters.Counters[3].WarningBit )
      Contact( "DB_M001_HMI".MaintenanceCounters.Counters[3].Reset )
      R_Coil( "DB_M001_HMI".MaintenanceCounters.Counters[3].WarningBit )
   END_RUNG
   RUNG wire#powerrail
      Mul(in1 := "DB_M001_HMI".MaintenanceCounters.Counters[3].MaintenanceThreshold, in2 := 60, out => #Threshold[3])
      #Maintenance[3]("Counter" := "DB_M001_Status"."ISC-CAM".Datacollection.BeltRunTime, Threshold := #Threshold[3], Maintenance := "DB_M001_HMI".MaintenanceCounters.Counters[3].WarningBit, CountUnitlNextMaintenance => "DB_M001_HMI".MaintenanceCounters.Counters[3].MaintenanceCountUnitlNextMaintenance)
   END_RUNG
   // the same network as SCL:
   IF "DB_M001_HMI".MaintenanceCounters.Counters[3].WarningBit AND "DB_M001_HMI".MaintenanceCounters.Counters[3].Reset THEN
       "DB_M001_HMI".MaintenanceCounters.Counters[3].WarningBit := FALSE;
   END_IF;
   #Threshold[3] := "DB_M001_HMI".MaintenanceCounters.Counters[3].MaintenanceThreshold * 60;
   #Maintenance[3]("Counter" := "DB_M001_Status"."ISC-CAM".Datacollection.BeltRunTime,   // "FB_ISC-CAM_Maintenance"
                   Threshold := #Threshold[3],
                   Maintenance := "DB_M001_HMI".MaintenanceCounters.Counters[3].WarningBit,
                   CountUnitlNextMaintenance => "DB_M001_HMI".MaintenanceCounters.Counters[3].MaintenanceCountUnitlNextMaintenance);
END_REGION

REGION Network 6: Maintenance counter. Belt run time - transfer rollers.
   RUNG wire#powerrail
      Contact( "DB_M001_HMI".MaintenanceCounters.Counters[4].WarningBit )
      Contact( "DB_M001_HMI".MaintenanceCounters.Counters[4].Reset )
      R_Coil( "DB_M001_HMI".MaintenanceCounters.Counters[4].WarningBit )
   END_RUNG
   RUNG wire#powerrail
      Mul(in1 := "DB_M001_HMI".MaintenanceCounters.Counters[4].MaintenanceThreshold, in2 := 60, out => #Threshold[4])
      #Maintenance[4]("Counter" := "DB_M001_Status"."ISC-CAM".Datacollection.BeltRunTime, Threshold := #Threshold[4], Maintenance := "DB_M001_HMI".MaintenanceCounters.Counters[4].WarningBit, CountUnitlNextMaintenance => "DB_M001_HMI".MaintenanceCounters.Counters[4].MaintenanceCountUnitlNextMaintenance)
   END_RUNG
   // the same network as SCL:
   IF "DB_M001_HMI".MaintenanceCounters.Counters[4].WarningBit AND "DB_M001_HMI".MaintenanceCounters.Counters[4].Reset THEN
       "DB_M001_HMI".MaintenanceCounters.Counters[4].WarningBit := FALSE;
   END_IF;
   #Threshold[4] := "DB_M001_HMI".MaintenanceCounters.Counters[4].MaintenanceThreshold * 60;
   #Maintenance[4]("Counter" := "DB_M001_Status"."ISC-CAM".Datacollection.BeltRunTime,   // "FB_ISC-CAM_Maintenance"
                   Threshold := #Threshold[4],
                   Maintenance := "DB_M001_HMI".MaintenanceCounters.Counters[4].WarningBit,
                   CountUnitlNextMaintenance => "DB_M001_HMI".MaintenanceCounters.Counters[4].MaintenanceCountUnitlNextMaintenance);
END_REGION

REGION Network 7: Maintenance counter. Belt run time - return rollers.
   RUNG wire#powerrail
      Contact( "DB_M001_HMI".MaintenanceCounters.Counters[5].WarningBit )
      Contact( "DB_M001_HMI".MaintenanceCounters.Counters[5].Reset )
      R_Coil( "DB_M001_HMI".MaintenanceCounters.Counters[5].WarningBit )
   END_RUNG
   RUNG wire#powerrail
      Mul(in1 := "DB_M001_HMI".MaintenanceCounters.Counters[5].MaintenanceThreshold, in2 := 60, out => #Threshold[5])
      #Maintenance[5]("Counter" := "DB_M001_Status"."ISC-CAM".Datacollection.BeltRunTime, Threshold := #Threshold[5], Maintenance := "DB_M001_HMI".MaintenanceCounters.Counters[5].WarningBit, CountUnitlNextMaintenance => "DB_M001_HMI".MaintenanceCounters.Counters[5].MaintenanceCountUnitlNextMaintenance)
   END_RUNG
   // the same network as SCL:
   IF "DB_M001_HMI".MaintenanceCounters.Counters[5].WarningBit AND "DB_M001_HMI".MaintenanceCounters.Counters[5].Reset THEN
       "DB_M001_HMI".MaintenanceCounters.Counters[5].WarningBit := FALSE;
   END_IF;
   #Threshold[5] := "DB_M001_HMI".MaintenanceCounters.Counters[5].MaintenanceThreshold * 60;
   #Maintenance[5]("Counter" := "DB_M001_Status"."ISC-CAM".Datacollection.BeltRunTime,   // "FB_ISC-CAM_Maintenance"
                   Threshold := #Threshold[5],
                   Maintenance := "DB_M001_HMI".MaintenanceCounters.Counters[5].WarningBit,
                   CountUnitlNextMaintenance => "DB_M001_HMI".MaintenanceCounters.Counters[5].MaintenanceCountUnitlNextMaintenance);
END_REGION

REGION Network 8: Maintenance counter. Belt run time - oil level drive motor.
   RUNG wire#powerrail
      Contact( "DB_M001_HMI".MaintenanceCounters.Counters[6].WarningBit )
      Contact( "DB_M001_HMI".MaintenanceCounters.Counters[6].Reset )
      R_Coil( "DB_M001_HMI".MaintenanceCounters.Counters[6].WarningBit )
   END_RUNG
   RUNG wire#powerrail
      Mul(in1 := "DB_M001_HMI".MaintenanceCounters.Counters[6].MaintenanceThreshold, in2 := 60, out => #Threshold[6])
      #Maintenance[6]("Counter" := "DB_M001_Status"."ISC-CAM".Datacollection.BeltRunTime, Threshold := #Threshold[6], Maintenance := "DB_M001_HMI".MaintenanceCounters.Counters[6].WarningBit, CountUnitlNextMaintenance => "DB_M001_HMI".MaintenanceCounters.Counters[6].MaintenanceCountUnitlNextMaintenance)
   END_RUNG
   // the same network as SCL:
   IF "DB_M001_HMI".MaintenanceCounters.Counters[6].WarningBit AND "DB_M001_HMI".MaintenanceCounters.Counters[6].Reset THEN
       "DB_M001_HMI".MaintenanceCounters.Counters[6].WarningBit := FALSE;
   END_IF;
   #Threshold[6] := "DB_M001_HMI".MaintenanceCounters.Counters[6].MaintenanceThreshold * 60;
   #Maintenance[6]("Counter" := "DB_M001_Status"."ISC-CAM".Datacollection.BeltRunTime,   // "FB_ISC-CAM_Maintenance"
                   Threshold := #Threshold[6],
                   Maintenance := "DB_M001_HMI".MaintenanceCounters.Counters[6].WarningBit,
                   CountUnitlNextMaintenance => "DB_M001_HMI".MaintenanceCounters.Counters[6].MaintenanceCountUnitlNextMaintenance);
END_REGION

REGION Network 9: Maintenance counter. Pop up cylinder activations - cylinder movement, wear and contaminants, zone 0
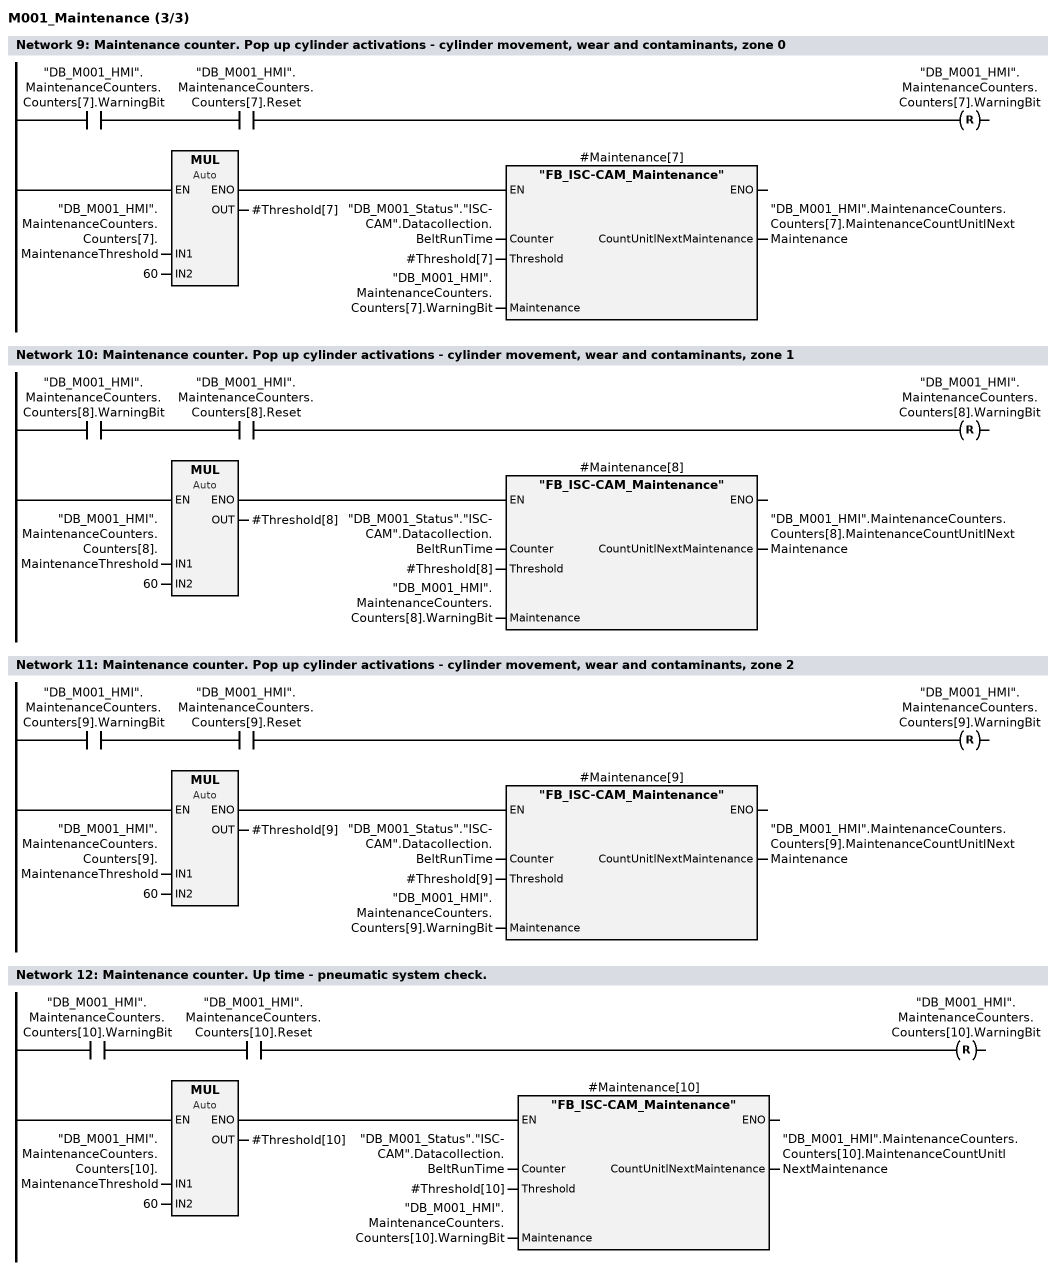
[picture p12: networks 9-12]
   RUNG wire#powerrail
      Contact( "DB_M001_HMI".MaintenanceCounters.Counters[7].WarningBit )
      Contact( "DB_M001_HMI".MaintenanceCounters.Counters[7].Reset )
      R_Coil( "DB_M001_HMI".MaintenanceCounters.Counters[7].WarningBit )
   END_RUNG
   RUNG wire#powerrail
      Mul(in1 := "DB_M001_HMI".MaintenanceCounters.Counters[7].MaintenanceThreshold, in2 := 60, out => #Threshold[7])
      #Maintenance[7]("Counter" := "DB_M001_Status"."ISC-CAM".Datacollection.BeltRunTime, Threshold := #Threshold[7], Maintenance := "DB_M001_HMI".MaintenanceCounters.Counters[7].WarningBit, CountUnitlNextMaintenance => "DB_M001_HMI".MaintenanceCounters.Counters[7].MaintenanceCountUnitlNextMaintenance)
   END_RUNG
   // the same network as SCL:
   IF "DB_M001_HMI".MaintenanceCounters.Counters[7].WarningBit AND "DB_M001_HMI".MaintenanceCounters.Counters[7].Reset THEN
       "DB_M001_HMI".MaintenanceCounters.Counters[7].WarningBit := FALSE;
   END_IF;
   #Threshold[7] := "DB_M001_HMI".MaintenanceCounters.Counters[7].MaintenanceThreshold * 60;
   #Maintenance[7]("Counter" := "DB_M001_Status"."ISC-CAM".Datacollection.BeltRunTime,   // "FB_ISC-CAM_Maintenance"
                   Threshold := #Threshold[7],
                   Maintenance := "DB_M001_HMI".MaintenanceCounters.Counters[7].WarningBit,
                   CountUnitlNextMaintenance => "DB_M001_HMI".MaintenanceCounters.Counters[7].MaintenanceCountUnitlNextMaintenance);
END_REGION

REGION Network 10: Maintenance counter. Pop up cylinder activations - cylinder movement, wear and contaminants, zone 1
   RUNG wire#powerrail
      Contact( "DB_M001_HMI".MaintenanceCounters.Counters[8].WarningBit )
      Contact( "DB_M001_HMI".MaintenanceCounters.Counters[8].Reset )
      R_Coil( "DB_M001_HMI".MaintenanceCounters.Counters[8].WarningBit )
   END_RUNG
   RUNG wire#powerrail
      Mul(in1 := "DB_M001_HMI".MaintenanceCounters.Counters[8].MaintenanceThreshold, in2 := 60, out => #Threshold[8])
      #Maintenance[8]("Counter" := "DB_M001_Status"."ISC-CAM".Datacollection.BeltRunTime, Threshold := #Threshold[8], Maintenance := "DB_M001_HMI".MaintenanceCounters.Counters[8].WarningBit, CountUnitlNextMaintenance => "DB_M001_HMI".MaintenanceCounters.Counters[8].MaintenanceCountUnitlNextMaintenance)
   END_RUNG
   // the same network as SCL:
   IF "DB_M001_HMI".MaintenanceCounters.Counters[8].WarningBit AND "DB_M001_HMI".MaintenanceCounters.Counters[8].Reset THEN
       "DB_M001_HMI".MaintenanceCounters.Counters[8].WarningBit := FALSE;
   END_IF;
   #Threshold[8] := "DB_M001_HMI".MaintenanceCounters.Counters[8].MaintenanceThreshold * 60;
   #Maintenance[8]("Counter" := "DB_M001_Status"."ISC-CAM".Datacollection.BeltRunTime,   // "FB_ISC-CAM_Maintenance"
                   Threshold := #Threshold[8],
                   Maintenance := "DB_M001_HMI".MaintenanceCounters.Counters[8].WarningBit,
                   CountUnitlNextMaintenance => "DB_M001_HMI".MaintenanceCounters.Counters[8].MaintenanceCountUnitlNextMaintenance);
END_REGION

REGION Network 11: Maintenance counter. Pop up cylinder activations - cylinder movement, wear and contaminants, zone 2
   RUNG wire#powerrail
      Contact( "DB_M001_HMI".MaintenanceCounters.Counters[9].WarningBit )
      Contact( "DB_M001_HMI".MaintenanceCounters.Counters[9].Reset )
      R_Coil( "DB_M001_HMI".MaintenanceCounters.Counters[9].WarningBit )
   END_RUNG
   RUNG wire#powerrail
      Mul(in1 := "DB_M001_HMI".MaintenanceCounters.Counters[9].MaintenanceThreshold, in2 := 60, out => #Threshold[9])
      #Maintenance[9]("Counter" := "DB_M001_Status"."ISC-CAM".Datacollection.BeltRunTime, Threshold := #Threshold[9], Maintenance := "DB_M001_HMI".MaintenanceCounters.Counters[9].WarningBit, CountUnitlNextMaintenance => "DB_M001_HMI".MaintenanceCounters.Counters[9].MaintenanceCountUnitlNextMaintenance)
   END_RUNG
   // the same network as SCL:
   IF "DB_M001_HMI".MaintenanceCounters.Counters[9].WarningBit AND "DB_M001_HMI".MaintenanceCounters.Counters[9].Reset THEN
       "DB_M001_HMI".MaintenanceCounters.Counters[9].WarningBit := FALSE;
   END_IF;
   #Threshold[9] := "DB_M001_HMI".MaintenanceCounters.Counters[9].MaintenanceThreshold * 60;
   #Maintenance[9]("Counter" := "DB_M001_Status"."ISC-CAM".Datacollection.BeltRunTime,   // "FB_ISC-CAM_Maintenance"
                   Threshold := #Threshold[9],
                   Maintenance := "DB_M001_HMI".MaintenanceCounters.Counters[9].WarningBit,
                   CountUnitlNextMaintenance => "DB_M001_HMI".MaintenanceCounters.Counters[9].MaintenanceCountUnitlNextMaintenance);
END_REGION

REGION Network 12: Maintenance counter. Up time - pneumatic system check.
   RUNG wire#powerrail
      Contact( "DB_M001_HMI".MaintenanceCounters.Counters[10].WarningBit )
      Contact( "DB_M001_HMI".MaintenanceCounters.Counters[10].Reset )
      R_Coil( "DB_M001_HMI".MaintenanceCounters.Counters[10].WarningBit )
   END_RUNG
   RUNG wire#powerrail
      Mul(in1 := "DB_M001_HMI".MaintenanceCounters.Counters[10].MaintenanceThreshold, in2 := 60, out => #Threshold[10])
      #Maintenance[10]("Counter" := "DB_M001_Status"."ISC-CAM".Datacollection.BeltRunTime, Threshold := #Threshold[10], Maintenance := "DB_M001_HMI".MaintenanceCounters.Counters[10].WarningBit, CountUnitlNextMaintenance => "DB_M001_HMI".MaintenanceCounters.Counters[10].MaintenanceCountUnitlNextMaintenance)
   END_RUNG
   // the same network as SCL:
   IF "DB_M001_HMI".MaintenanceCounters.Counters[10].WarningBit AND "DB_M001_HMI".MaintenanceCounters.Counters[10].Reset THEN
       "DB_M001_HMI".MaintenanceCounters.Counters[10].WarningBit := FALSE;
   END_IF;
   #Threshold[10] := "DB_M001_HMI".MaintenanceCounters.Counters[10].MaintenanceThreshold * 60;
   #Maintenance[10]("Counter" := "DB_M001_Status"."ISC-CAM".Datacollection.BeltRunTime,   // "FB_ISC-CAM_Maintenance"
                    Threshold := #Threshold[10],
                    Maintenance := "DB_M001_HMI".MaintenanceCounters.Counters[10].WarningBit,
                    CountUnitlNextMaintenance => "DB_M001_HMI".MaintenanceCounters.Counters[10].MaintenanceCountUnitlNextMaintenance);
END_REGION
END_FUNCTION_BLOCK

// folder: 200-299_Machine_002

FUNCTION_BLOCK "M002_Faults"   // FB1, LAD
TITLE = Machine faults
{ S7_Optimized_Access := 'TRUE' }
VERSION : 0.1
   VAR
      sBool : Bool;
      FG0_Timer_00 : TON_TIME;
      FG0_Timer_01 : TON_TIME;
      Faultbits : "dt_ISCCAM_Alarms";
      faultCount AT Faultbits : DInt;
   END_VAR
BEGIN

REGION Network 1 (SCL): Faults
   //Fault group 0, ISC device state errors.
   //Group reset
   IF ("DB_General_HMI".GeneralResetBtnCmd) THEN
       "DB_M002_HMI".FaultBits.CommsAlarm := 0;
       "DB_M002_HMI".FaultBits.Fault0Alarm := 0;
       "DB_M002_HMI".FaultBits.Fault1Alarm := 0;
       "DB_M002_HMI".FaultBits.Fault2Alarm := 0;
       "DB_M002_HMI".FaultBits.Fault3Alarm := 0;
       "DB_M002_HMI".FaultBits.Fault4Alarm := 0;
       "DB_M002_HMI".FaultBits.Fault5Alarm := 0;
       "DB_M002_HMI".FaultBits.Fault6Alarm := 0;
       "DB_M002_HMI".FaultBits.Fault7Alarm := 0;
       "DB_M002_HMI".FaultBits.Fault8Alarm := 0;
       "DB_M002_HMI".FaultBits.Fault9Alarm := 0;
       "DB_M002_HMI".FaultBits.Fault10Alarm := 0;
       "DB_M002_HMI".FaultBits.Fault11Alarm := 0;
       "DB_M002_HMI".FaultBits.Fault12Alarm := 0;
       "DB_M002_HMI".FaultBits.Fault13Alarm := 0;
       "DB_M002_HMI".FaultBits.Fault14Alarm := 0;
       "DB_M002_HMI".FaultBits.Fault15Alarm := 0;
   END_IF;


   //Lifebit error
   #FG0_Timer_00(IN := NOT "DB_M002_Status"."ISC-CAM".Status.LifeBit,
                 PT := T#3s);
   #FG0_Timer_01(IN := "DB_M002_Status"."ISC-CAM".Status.LifeBit,
                 PT := T#3s);


   IF (NOT "DB_M002_HMI".FaultBits.CommsAlarm AND (#FG0_Timer_00.Q OR #FG0_Timer_01.Q)) THEN
       "DB_M002_HMI".FaultBits.CommsAlarm := 1;
   END_IF;

   IF (NOT "DB_M002_HMI".FaultBits.Fault0Alarm AND NOT "DB_M002_Status"."ISC-CAM".Status.FaultCode."FaultCode.0") THEN
       "DB_M002_HMI".FaultBits.Fault0Alarm := 1;
   END_IF;

   IF (NOT "DB_M002_HMI".FaultBits.Fault1Alarm AND NOT "DB_M002_Status"."ISC-CAM".Status.FaultCode."FaultCode.1") THEN
       "DB_M002_HMI".FaultBits.Fault1Alarm := 1;
   END_IF;

   IF (NOT "DB_M002_HMI".FaultBits.Fault2Alarm AND NOT "DB_M002_Status"."ISC-CAM".Status.FaultCode."FaultCode.2") THEN
       "DB_M002_HMI".FaultBits.Fault2Alarm := 1;
   END_IF;

   IF (NOT "DB_M002_HMI".FaultBits.Fault3Alarm AND NOT "DB_M002_Status"."ISC-CAM".Status.FaultCode."FaultCode.3") THEN
       "DB_M002_HMI".FaultBits.Fault3Alarm := 1;
   END_IF;

   IF (NOT "DB_M002_HMI".FaultBits.Fault4Alarm AND NOT "DB_M002_Status"."ISC-CAM".Status.FaultCode."FaultCode.4") THEN
       "DB_M002_HMI".FaultBits.Fault4Alarm := 1;
   END_IF;

   IF (NOT "DB_M002_HMI".FaultBits.Fault5Alarm AND NOT "DB_M002_Status"."ISC-CAM".Status.FaultCode."FaultCode.5") THEN
       "DB_M002_HMI".FaultBits.Fault5Alarm := 1;
   END_IF;

   IF (NOT "DB_M002_HMI".FaultBits.Fault6Alarm AND NOT "DB_M002_Status"."ISC-CAM".Status.FaultCode."FaultCode.6") THEN
       "DB_M002_HMI".FaultBits.Fault6Alarm := 1;
   END_IF;

   IF (NOT "DB_M002_HMI".FaultBits.Fault7Alarm AND NOT "DB_M002_Status"."ISC-CAM".Status.FaultCode."FaultCode.7") THEN
       "DB_M002_HMI".FaultBits.Fault7Alarm := 1;
   END_IF;

   IF (NOT "DB_M002_HMI".FaultBits.Fault8Alarm AND NOT "DB_M002_Status"."ISC-CAM".Status.FaultCode."FaultCode.8") THEN
       "DB_M002_HMI".FaultBits.Fault8Alarm := 1;
   END_IF;

   IF (NOT "DB_M002_HMI".FaultBits.Fault9Alarm AND NOT "DB_M002_Status"."ISC-CAM".Status.FaultCode."FaultCode.9") THEN
       "DB_M002_HMI".FaultBits.Fault9Alarm := 1;
   END_IF;

   IF (NOT "DB_M002_HMI".FaultBits.Fault10Alarm AND NOT "DB_M002_Status"."ISC-CAM".Status.FaultCode."FaultCode.10") THEN
       "DB_M002_HMI".FaultBits.Fault10Alarm := 1;
   END_IF;

   IF (NOT "DB_M002_HMI".FaultBits.Fault11Alarm AND NOT "DB_M002_Status"."ISC-CAM".Status.FaultCode."FaultCode.11") THEN
       "DB_M002_HMI".FaultBits.Fault11Alarm := 1;
   END_IF;

   IF (NOT "DB_M002_HMI".FaultBits.Fault12Alarm AND NOT "DB_M002_Status"."ISC-CAM".Status.FaultCode."FaultCode.12") THEN
       "DB_M002_HMI".FaultBits.Fault12Alarm := 1;
   END_IF;

   IF (NOT "DB_M002_HMI".FaultBits.Fault13Alarm AND NOT "DB_M002_Status"."ISC-CAM".Status.FaultCode."FaultCode.13") THEN
       "DB_M002_HMI".FaultBits.Fault13Alarm := 1;
   END_IF;

   IF (NOT "DB_M002_HMI".FaultBits.Fault14Alarm AND NOT "DB_M002_Status"."ISC-CAM".Status.FaultCode."FaultCode.14") THEN
       "DB_M002_HMI".FaultBits.Fault14Alarm := 1;
   END_IF;

   IF (NOT "DB_M002_HMI".FaultBits.Fault15Alarm AND NOT "DB_M002_Status"."ISC-CAM".Status.FaultCode."FaultCode.15") THEN
       "DB_M002_HMI".FaultBits.Fault15Alarm := 1;
   END_IF;

   //Fault count
   #Faultbits := "DB_M002_HMI".FaultBits;

   IF (#faultCount > 0 AND NOT "DB_M002_HMI".Fault) THEN
       "DB_M002_HMI".Fault := 1;
   ELSIF #faultCount = 0 AND "DB_M002_HMI".Fault THEN
       "DB_M002_HMI".Fault := 0;
   END_IF;
END_REGION
END_FUNCTION_BLOCK

FUNCTION_BLOCK "M002_Main"   // FB3, LAD
TITLE = Main Machine routine.
{ S7_Optimized_Access := 'TRUE' }
VERSION : 0.1
   VAR
      Faults : "M002_Faults";
      Maintenance : "M002_Maintenance";
      EncSim : "Encoder";
      PE : "PhotoEye";
      "ISC-CAM_Comm" : "FB_ISC-CAM_Comm";
      Diagonistics : DIS;
      RET_VAL : Int;
      CNT_DIAG : UInt;
   END_VAR
BEGIN

REGION Network 1: Communication status
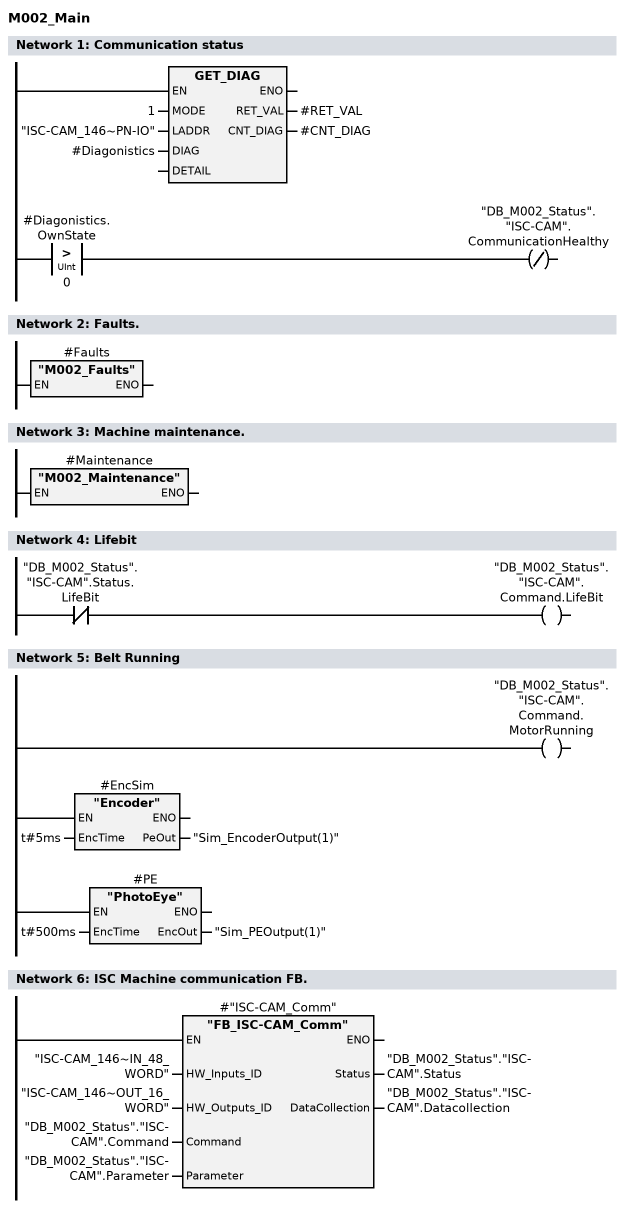
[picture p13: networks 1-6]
   #RET_VAL := GET_DIAG(MODE := 1, LADDR := "ISC-CAM_146~PN-IO", DIAG := #Diagonistics, CNT_DIAG => #CNT_DIAG);
   "DB_M002_Status"."ISC-CAM".CommunicationHealthy := NOT (#Diagonistics.OwnState > 0);
END_REGION

REGION Network 2: Faults.
   RUNG wire#powerrail
      #Faults()
   END_RUNG
   // the same network as SCL:
   #Faults();   // "M002_Faults"
END_REGION

REGION Network 3: Machine maintenance.
   RUNG wire#powerrail
      #Maintenance()
   END_RUNG
   // the same network as SCL:
   #Maintenance();   // "M002_Maintenance"
END_REGION

REGION Network 4: Lifebit
   RUNG wire#powerrail
      I_Contact( "DB_M002_Status"."ISC-CAM".Status.LifeBit )
      Coil( "DB_M002_Status"."ISC-CAM".Command.LifeBit )
   END_RUNG
   // the same network as SCL:
   "DB_M002_Status"."ISC-CAM".Command.LifeBit := NOT "DB_M002_Status"."ISC-CAM".Status.LifeBit;
END_REGION

REGION Network 5: Belt Running
   RUNG wire#powerrail
      Coil( "DB_M002_Status"."ISC-CAM".Command.MotorRunning )
   END_RUNG
   RUNG wire#powerrail
      #EncSim(EncTime := t#5ms, PeOut => "Sim_EncoderOutput(1)")
   END_RUNG
   RUNG wire#powerrail
      #PE(EncTime := t#500ms, EncOut => "Sim_PEOutput(1)")
   END_RUNG
   // the same network as SCL:
   "DB_M002_Status"."ISC-CAM".Command.MotorRunning := TRUE;
   #EncSim(EncTime := t#5ms, PeOut => "Sim_EncoderOutput(1)");   // "Encoder"
   #PE(EncTime := t#500ms, EncOut => "Sim_PEOutput(1)");   // "PhotoEye"
END_REGION

REGION Network 6: ISC Machine communication FB.
   RUNG wire#powerrail
      #"ISC-CAM_Comm"(HW_Inputs_ID := "ISC-CAM_146~IN_48_WORD", HW_Outputs_ID := "ISC-CAM_146~OUT_16_WORD", Command := "DB_M002_Status"."ISC-CAM".Command, Parameter := "DB_M002_Status"."ISC-CAM".Parameter, Status => "DB_M002_Status"."ISC-CAM".Status, DataCollection => "DB_M002_Status"."ISC-CAM".Datacollection)
   END_RUNG
   // the same network as SCL:
   #"ISC-CAM_Comm"(HW_Inputs_ID := "ISC-CAM_146~IN_48_WORD",   // "FB_ISC-CAM_Comm"
                   HW_Outputs_ID := "ISC-CAM_146~OUT_16_WORD",
                   Command := "DB_M002_Status"."ISC-CAM".Command,
                   Parameter := "DB_M002_Status"."ISC-CAM".Parameter,
                   Status => "DB_M002_Status"."ISC-CAM".Status,
                   DataCollection => "DB_M002_Status"."ISC-CAM".Datacollection);
END_REGION
END_FUNCTION_BLOCK

FUNCTION_BLOCK "M002_Maintenance"   // FB4, LAD
TITLE = Machine maintenance.
{ S7_Optimized_Access := 'TRUE' }
VERSION : 0.1
   VAR
      Maintenance : Array[0..15] of "FB_ISC-CAM_Maintenance";
      Threshold : Array[0..15] of DInt;
   END_VAR
BEGIN

REGION Network 1: Simulation only.
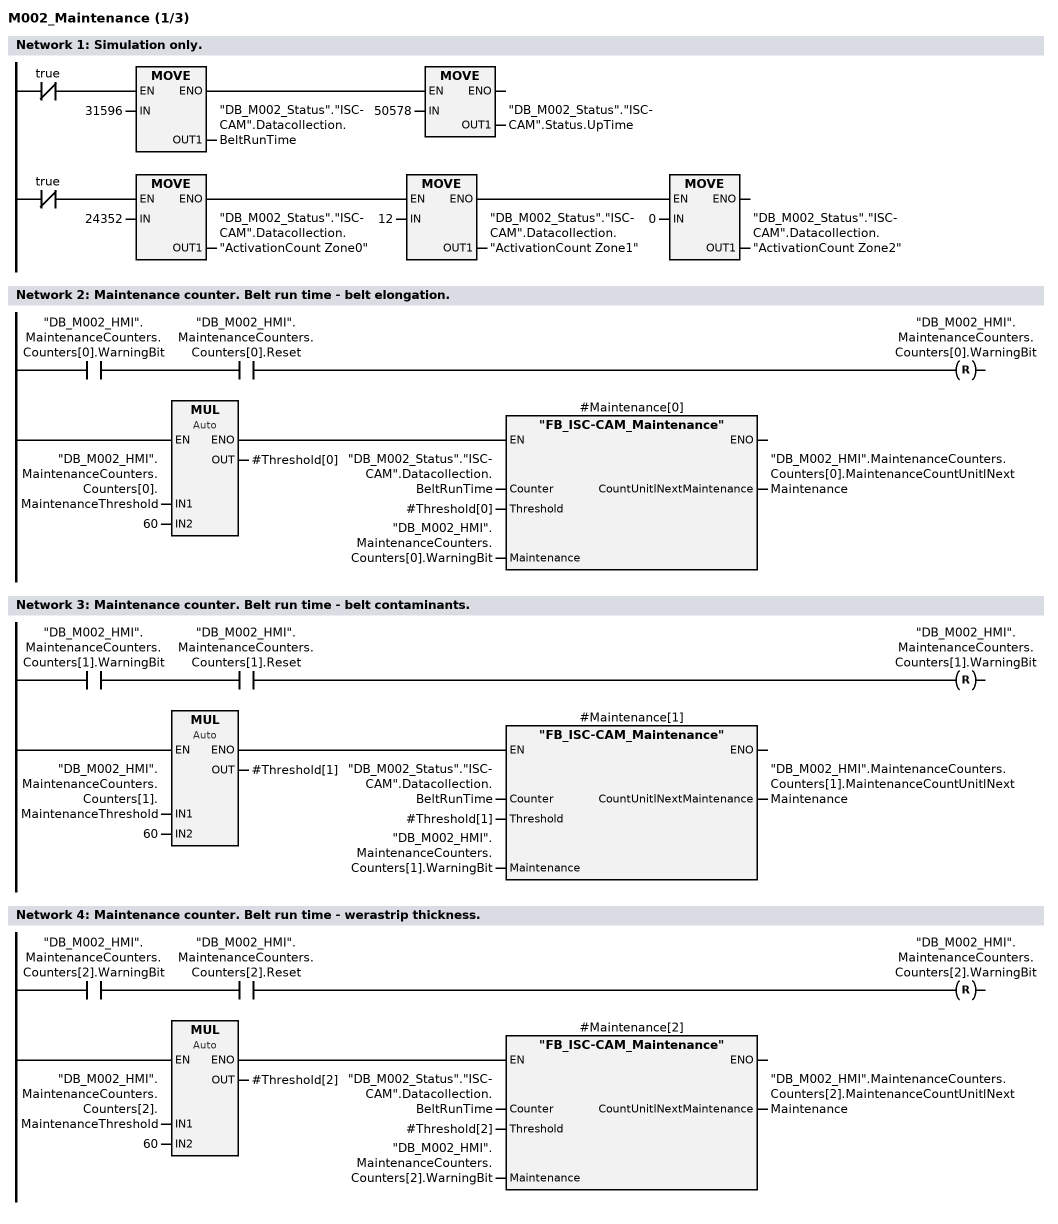
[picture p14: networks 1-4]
   RUNG wire#powerrail
      I_Contact( true )
      Move(in := 31596, out1 => "DB_M002_Status"."ISC-CAM".Datacollection.BeltRunTime)
      Move(in := 50578, out1 => "DB_M002_Status"."ISC-CAM".Status.UpTime)
   END_RUNG
   RUNG wire#powerrail
      I_Contact( true )
      Move(in := 24352, out1 => "DB_M002_Status"."ISC-CAM".Datacollection."ActivationCount Zone0")
      Move(in := 12, out1 => "DB_M002_Status"."ISC-CAM".Datacollection."ActivationCount Zone1")
      Move(in := 0, out1 => "DB_M002_Status"."ISC-CAM".Datacollection."ActivationCount Zone2")
   END_RUNG
   // the same network as SCL:
   IF NOT true THEN
       "DB_M002_Status"."ISC-CAM".Datacollection.BeltRunTime := 31596;
       "DB_M002_Status"."ISC-CAM".Status.UpTime := 50578;
       "DB_M002_Status"."ISC-CAM".Datacollection."ActivationCount Zone0" := 24352;
       "DB_M002_Status"."ISC-CAM".Datacollection."ActivationCount Zone1" := 12;
       "DB_M002_Status"."ISC-CAM".Datacollection."ActivationCount Zone2" := 0;
   END_IF;
END_REGION

REGION Network 2: Maintenance counter. Belt run time - belt elongation.
   RUNG wire#powerrail
      Contact( "DB_M002_HMI".MaintenanceCounters.Counters[0].WarningBit )
      Contact( "DB_M002_HMI".MaintenanceCounters.Counters[0].Reset )
      R_Coil( "DB_M002_HMI".MaintenanceCounters.Counters[0].WarningBit )
   END_RUNG
   RUNG wire#powerrail
      Mul(in1 := "DB_M002_HMI".MaintenanceCounters.Counters[0].MaintenanceThreshold, in2 := 60, out => #Threshold[0])
      #Maintenance[0]("Counter" := "DB_M002_Status"."ISC-CAM".Datacollection.BeltRunTime, Threshold := #Threshold[0], Maintenance := "DB_M002_HMI".MaintenanceCounters.Counters[0].WarningBit, CountUnitlNextMaintenance => "DB_M002_HMI".MaintenanceCounters.Counters[0].MaintenanceCountUnitlNextMaintenance)
   END_RUNG
   // the same network as SCL:
   IF "DB_M002_HMI".MaintenanceCounters.Counters[0].WarningBit AND "DB_M002_HMI".MaintenanceCounters.Counters[0].Reset THEN
       "DB_M002_HMI".MaintenanceCounters.Counters[0].WarningBit := FALSE;
   END_IF;
   #Threshold[0] := "DB_M002_HMI".MaintenanceCounters.Counters[0].MaintenanceThreshold * 60;
   #Maintenance[0]("Counter" := "DB_M002_Status"."ISC-CAM".Datacollection.BeltRunTime,   // "FB_ISC-CAM_Maintenance"
                   Threshold := #Threshold[0],
                   Maintenance := "DB_M002_HMI".MaintenanceCounters.Counters[0].WarningBit,
                   CountUnitlNextMaintenance => "DB_M002_HMI".MaintenanceCounters.Counters[0].MaintenanceCountUnitlNextMaintenance);
END_REGION

REGION Network 3: Maintenance counter. Belt run time - belt contaminants.
   RUNG wire#powerrail
      Contact( "DB_M002_HMI".MaintenanceCounters.Counters[1].WarningBit )
      Contact( "DB_M002_HMI".MaintenanceCounters.Counters[1].Reset )
      R_Coil( "DB_M002_HMI".MaintenanceCounters.Counters[1].WarningBit )
   END_RUNG
   RUNG wire#powerrail
      Mul(in1 := "DB_M002_HMI".MaintenanceCounters.Counters[1].MaintenanceThreshold, in2 := 60, out => #Threshold[1])
      #Maintenance[1]("Counter" := "DB_M002_Status"."ISC-CAM".Datacollection.BeltRunTime, Threshold := #Threshold[1], Maintenance := "DB_M002_HMI".MaintenanceCounters.Counters[1].WarningBit, CountUnitlNextMaintenance => "DB_M002_HMI".MaintenanceCounters.Counters[1].MaintenanceCountUnitlNextMaintenance)
   END_RUNG
   // the same network as SCL:
   IF "DB_M002_HMI".MaintenanceCounters.Counters[1].WarningBit AND "DB_M002_HMI".MaintenanceCounters.Counters[1].Reset THEN
       "DB_M002_HMI".MaintenanceCounters.Counters[1].WarningBit := FALSE;
   END_IF;
   #Threshold[1] := "DB_M002_HMI".MaintenanceCounters.Counters[1].MaintenanceThreshold * 60;
   #Maintenance[1]("Counter" := "DB_M002_Status"."ISC-CAM".Datacollection.BeltRunTime,   // "FB_ISC-CAM_Maintenance"
                   Threshold := #Threshold[1],
                   Maintenance := "DB_M002_HMI".MaintenanceCounters.Counters[1].WarningBit,
                   CountUnitlNextMaintenance => "DB_M002_HMI".MaintenanceCounters.Counters[1].MaintenanceCountUnitlNextMaintenance);
END_REGION

REGION Network 4: Maintenance counter. Belt run time - werastrip thickness.
   RUNG wire#powerrail
      Contact( "DB_M002_HMI".MaintenanceCounters.Counters[2].WarningBit )
      Contact( "DB_M002_HMI".MaintenanceCounters.Counters[2].Reset )
      R_Coil( "DB_M002_HMI".MaintenanceCounters.Counters[2].WarningBit )
   END_RUNG
   RUNG wire#powerrail
      Mul(in1 := "DB_M002_HMI".MaintenanceCounters.Counters[2].MaintenanceThreshold, in2 := 60, out => #Threshold[2])
      #Maintenance[2]("Counter" := "DB_M002_Status"."ISC-CAM".Datacollection.BeltRunTime, Threshold := #Threshold[2], Maintenance := "DB_M002_HMI".MaintenanceCounters.Counters[2].WarningBit, CountUnitlNextMaintenance => "DB_M002_HMI".MaintenanceCounters.Counters[2].MaintenanceCountUnitlNextMaintenance)
   END_RUNG
   // the same network as SCL:
   IF "DB_M002_HMI".MaintenanceCounters.Counters[2].WarningBit AND "DB_M002_HMI".MaintenanceCounters.Counters[2].Reset THEN
       "DB_M002_HMI".MaintenanceCounters.Counters[2].WarningBit := FALSE;
   END_IF;
   #Threshold[2] := "DB_M002_HMI".MaintenanceCounters.Counters[2].MaintenanceThreshold * 60;
   #Maintenance[2]("Counter" := "DB_M002_Status"."ISC-CAM".Datacollection.BeltRunTime,   // "FB_ISC-CAM_Maintenance"
                   Threshold := #Threshold[2],
                   Maintenance := "DB_M002_HMI".MaintenanceCounters.Counters[2].WarningBit,
                   CountUnitlNextMaintenance => "DB_M002_HMI".MaintenanceCounters.Counters[2].MaintenanceCountUnitlNextMaintenance);
END_REGION

REGION Network 5: Maintenance counter. Belt run time - helix rollers.
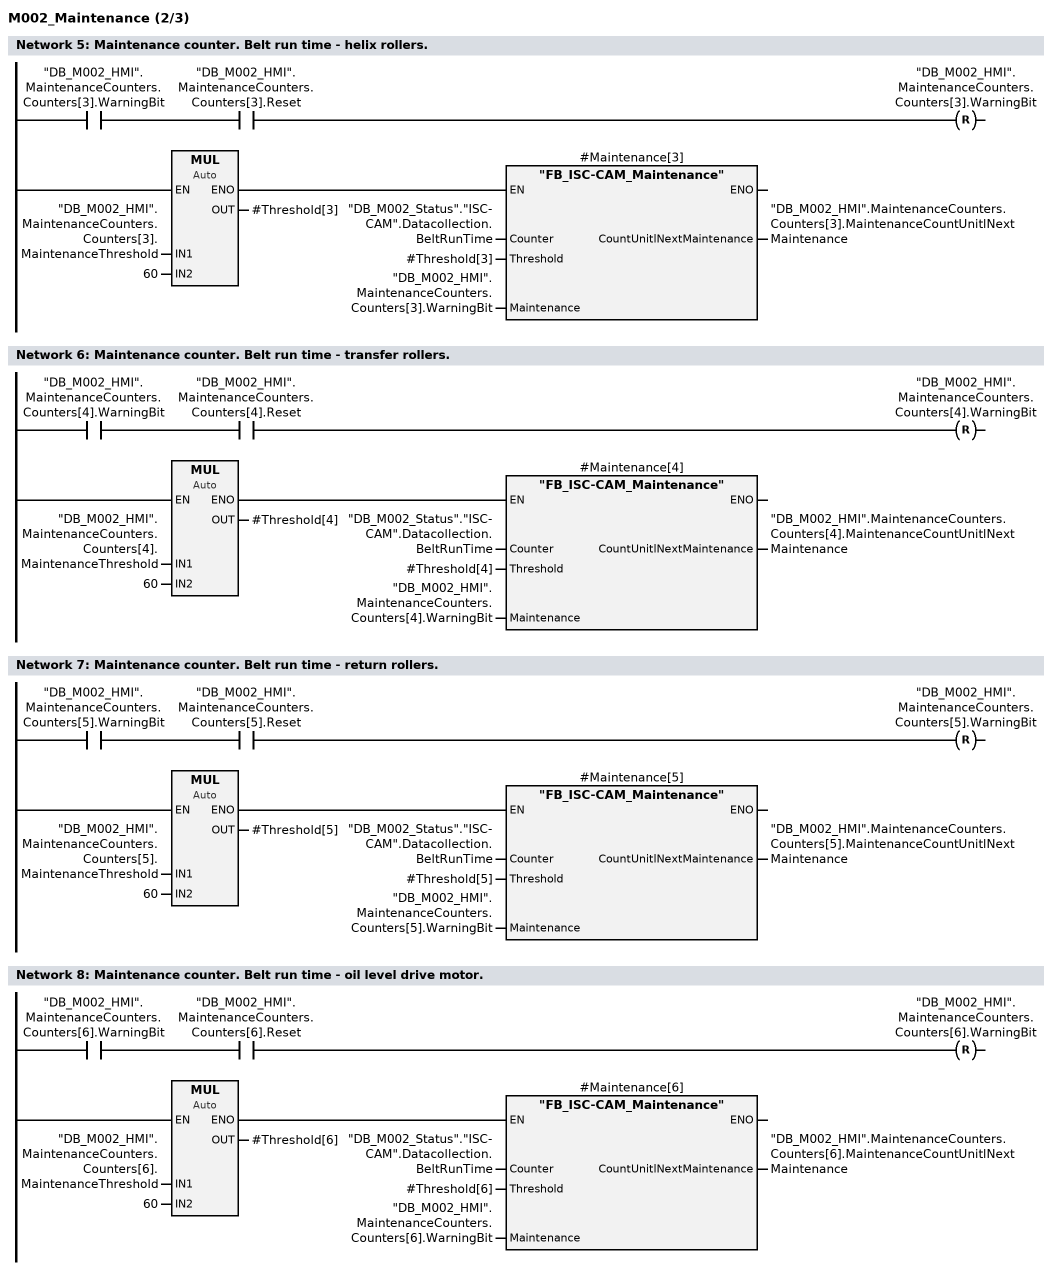
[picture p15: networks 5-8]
   RUNG wire#powerrail
      Contact( "DB_M002_HMI".MaintenanceCounters.Counters[3].WarningBit )
      Contact( "DB_M002_HMI".MaintenanceCounters.Counters[3].Reset )
      R_Coil( "DB_M002_HMI".MaintenanceCounters.Counters[3].WarningBit )
   END_RUNG
   RUNG wire#powerrail
      Mul(in1 := "DB_M002_HMI".MaintenanceCounters.Counters[3].MaintenanceThreshold, in2 := 60, out => #Threshold[3])
      #Maintenance[3]("Counter" := "DB_M002_Status"."ISC-CAM".Datacollection.BeltRunTime, Threshold := #Threshold[3], Maintenance := "DB_M002_HMI".MaintenanceCounters.Counters[3].WarningBit, CountUnitlNextMaintenance => "DB_M002_HMI".MaintenanceCounters.Counters[3].MaintenanceCountUnitlNextMaintenance)
   END_RUNG
   // the same network as SCL:
   IF "DB_M002_HMI".MaintenanceCounters.Counters[3].WarningBit AND "DB_M002_HMI".MaintenanceCounters.Counters[3].Reset THEN
       "DB_M002_HMI".MaintenanceCounters.Counters[3].WarningBit := FALSE;
   END_IF;
   #Threshold[3] := "DB_M002_HMI".MaintenanceCounters.Counters[3].MaintenanceThreshold * 60;
   #Maintenance[3]("Counter" := "DB_M002_Status"."ISC-CAM".Datacollection.BeltRunTime,   // "FB_ISC-CAM_Maintenance"
                   Threshold := #Threshold[3],
                   Maintenance := "DB_M002_HMI".MaintenanceCounters.Counters[3].WarningBit,
                   CountUnitlNextMaintenance => "DB_M002_HMI".MaintenanceCounters.Counters[3].MaintenanceCountUnitlNextMaintenance);
END_REGION

REGION Network 6: Maintenance counter. Belt run time - transfer rollers.
   RUNG wire#powerrail
      Contact( "DB_M002_HMI".MaintenanceCounters.Counters[4].WarningBit )
      Contact( "DB_M002_HMI".MaintenanceCounters.Counters[4].Reset )
      R_Coil( "DB_M002_HMI".MaintenanceCounters.Counters[4].WarningBit )
   END_RUNG
   RUNG wire#powerrail
      Mul(in1 := "DB_M002_HMI".MaintenanceCounters.Counters[4].MaintenanceThreshold, in2 := 60, out => #Threshold[4])
      #Maintenance[4]("Counter" := "DB_M002_Status"."ISC-CAM".Datacollection.BeltRunTime, Threshold := #Threshold[4], Maintenance := "DB_M002_HMI".MaintenanceCounters.Counters[4].WarningBit, CountUnitlNextMaintenance => "DB_M002_HMI".MaintenanceCounters.Counters[4].MaintenanceCountUnitlNextMaintenance)
   END_RUNG
   // the same network as SCL:
   IF "DB_M002_HMI".MaintenanceCounters.Counters[4].WarningBit AND "DB_M002_HMI".MaintenanceCounters.Counters[4].Reset THEN
       "DB_M002_HMI".MaintenanceCounters.Counters[4].WarningBit := FALSE;
   END_IF;
   #Threshold[4] := "DB_M002_HMI".MaintenanceCounters.Counters[4].MaintenanceThreshold * 60;
   #Maintenance[4]("Counter" := "DB_M002_Status"."ISC-CAM".Datacollection.BeltRunTime,   // "FB_ISC-CAM_Maintenance"
                   Threshold := #Threshold[4],
                   Maintenance := "DB_M002_HMI".MaintenanceCounters.Counters[4].WarningBit,
                   CountUnitlNextMaintenance => "DB_M002_HMI".MaintenanceCounters.Counters[4].MaintenanceCountUnitlNextMaintenance);
END_REGION

REGION Network 7: Maintenance counter. Belt run time - return rollers.
   RUNG wire#powerrail
      Contact( "DB_M002_HMI".MaintenanceCounters.Counters[5].WarningBit )
      Contact( "DB_M002_HMI".MaintenanceCounters.Counters[5].Reset )
      R_Coil( "DB_M002_HMI".MaintenanceCounters.Counters[5].WarningBit )
   END_RUNG
   RUNG wire#powerrail
      Mul(in1 := "DB_M002_HMI".MaintenanceCounters.Counters[5].MaintenanceThreshold, in2 := 60, out => #Threshold[5])
      #Maintenance[5]("Counter" := "DB_M002_Status"."ISC-CAM".Datacollection.BeltRunTime, Threshold := #Threshold[5], Maintenance := "DB_M002_HMI".MaintenanceCounters.Counters[5].WarningBit, CountUnitlNextMaintenance => "DB_M002_HMI".MaintenanceCounters.Counters[5].MaintenanceCountUnitlNextMaintenance)
   END_RUNG
   // the same network as SCL:
   IF "DB_M002_HMI".MaintenanceCounters.Counters[5].WarningBit AND "DB_M002_HMI".MaintenanceCounters.Counters[5].Reset THEN
       "DB_M002_HMI".MaintenanceCounters.Counters[5].WarningBit := FALSE;
   END_IF;
   #Threshold[5] := "DB_M002_HMI".MaintenanceCounters.Counters[5].MaintenanceThreshold * 60;
   #Maintenance[5]("Counter" := "DB_M002_Status"."ISC-CAM".Datacollection.BeltRunTime,   // "FB_ISC-CAM_Maintenance"
                   Threshold := #Threshold[5],
                   Maintenance := "DB_M002_HMI".MaintenanceCounters.Counters[5].WarningBit,
                   CountUnitlNextMaintenance => "DB_M002_HMI".MaintenanceCounters.Counters[5].MaintenanceCountUnitlNextMaintenance);
END_REGION

REGION Network 8: Maintenance counter. Belt run time - oil level drive motor.
   RUNG wire#powerrail
      Contact( "DB_M002_HMI".MaintenanceCounters.Counters[6].WarningBit )
      Contact( "DB_M002_HMI".MaintenanceCounters.Counters[6].Reset )
      R_Coil( "DB_M002_HMI".MaintenanceCounters.Counters[6].WarningBit )
   END_RUNG
   RUNG wire#powerrail
      Mul(in1 := "DB_M002_HMI".MaintenanceCounters.Counters[6].MaintenanceThreshold, in2 := 60, out => #Threshold[6])
      #Maintenance[6]("Counter" := "DB_M002_Status"."ISC-CAM".Datacollection.BeltRunTime, Threshold := #Threshold[6], Maintenance := "DB_M002_HMI".MaintenanceCounters.Counters[6].WarningBit, CountUnitlNextMaintenance => "DB_M002_HMI".MaintenanceCounters.Counters[6].MaintenanceCountUnitlNextMaintenance)
   END_RUNG
   // the same network as SCL:
   IF "DB_M002_HMI".MaintenanceCounters.Counters[6].WarningBit AND "DB_M002_HMI".MaintenanceCounters.Counters[6].Reset THEN
       "DB_M002_HMI".MaintenanceCounters.Counters[6].WarningBit := FALSE;
   END_IF;
   #Threshold[6] := "DB_M002_HMI".MaintenanceCounters.Counters[6].MaintenanceThreshold * 60;
   #Maintenance[6]("Counter" := "DB_M002_Status"."ISC-CAM".Datacollection.BeltRunTime,   // "FB_ISC-CAM_Maintenance"
                   Threshold := #Threshold[6],
                   Maintenance := "DB_M002_HMI".MaintenanceCounters.Counters[6].WarningBit,
                   CountUnitlNextMaintenance => "DB_M002_HMI".MaintenanceCounters.Counters[6].MaintenanceCountUnitlNextMaintenance);
END_REGION

REGION Network 9: Maintenance counter. Pop up cylinder activations - cylinder movement, wear and contaminants, zone 0
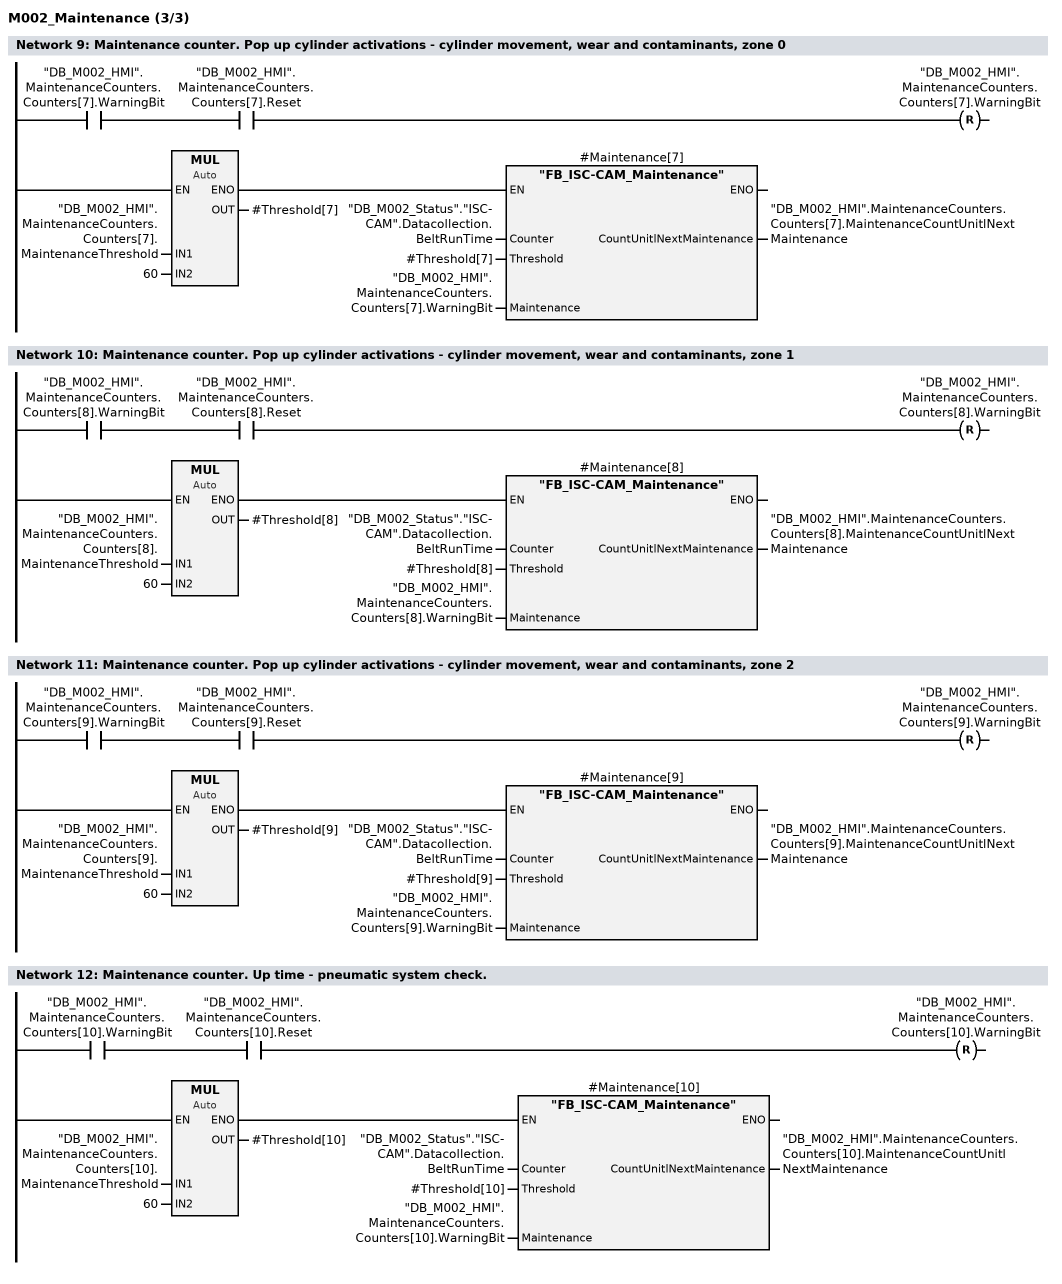
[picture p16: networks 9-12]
   RUNG wire#powerrail
      Contact( "DB_M002_HMI".MaintenanceCounters.Counters[7].WarningBit )
      Contact( "DB_M002_HMI".MaintenanceCounters.Counters[7].Reset )
      R_Coil( "DB_M002_HMI".MaintenanceCounters.Counters[7].WarningBit )
   END_RUNG
   RUNG wire#powerrail
      Mul(in1 := "DB_M002_HMI".MaintenanceCounters.Counters[7].MaintenanceThreshold, in2 := 60, out => #Threshold[7])
      #Maintenance[7]("Counter" := "DB_M002_Status"."ISC-CAM".Datacollection.BeltRunTime, Threshold := #Threshold[7], Maintenance := "DB_M002_HMI".MaintenanceCounters.Counters[7].WarningBit, CountUnitlNextMaintenance => "DB_M002_HMI".MaintenanceCounters.Counters[7].MaintenanceCountUnitlNextMaintenance)
   END_RUNG
   // the same network as SCL:
   IF "DB_M002_HMI".MaintenanceCounters.Counters[7].WarningBit AND "DB_M002_HMI".MaintenanceCounters.Counters[7].Reset THEN
       "DB_M002_HMI".MaintenanceCounters.Counters[7].WarningBit := FALSE;
   END_IF;
   #Threshold[7] := "DB_M002_HMI".MaintenanceCounters.Counters[7].MaintenanceThreshold * 60;
   #Maintenance[7]("Counter" := "DB_M002_Status"."ISC-CAM".Datacollection.BeltRunTime,   // "FB_ISC-CAM_Maintenance"
                   Threshold := #Threshold[7],
                   Maintenance := "DB_M002_HMI".MaintenanceCounters.Counters[7].WarningBit,
                   CountUnitlNextMaintenance => "DB_M002_HMI".MaintenanceCounters.Counters[7].MaintenanceCountUnitlNextMaintenance);
END_REGION

REGION Network 10: Maintenance counter. Pop up cylinder activations - cylinder movement, wear and contaminants, zone 1
   RUNG wire#powerrail
      Contact( "DB_M002_HMI".MaintenanceCounters.Counters[8].WarningBit )
      Contact( "DB_M002_HMI".MaintenanceCounters.Counters[8].Reset )
      R_Coil( "DB_M002_HMI".MaintenanceCounters.Counters[8].WarningBit )
   END_RUNG
   RUNG wire#powerrail
      Mul(in1 := "DB_M002_HMI".MaintenanceCounters.Counters[8].MaintenanceThreshold, in2 := 60, out => #Threshold[8])
      #Maintenance[8]("Counter" := "DB_M002_Status"."ISC-CAM".Datacollection.BeltRunTime, Threshold := #Threshold[8], Maintenance := "DB_M002_HMI".MaintenanceCounters.Counters[8].WarningBit, CountUnitlNextMaintenance => "DB_M002_HMI".MaintenanceCounters.Counters[8].MaintenanceCountUnitlNextMaintenance)
   END_RUNG
   // the same network as SCL:
   IF "DB_M002_HMI".MaintenanceCounters.Counters[8].WarningBit AND "DB_M002_HMI".MaintenanceCounters.Counters[8].Reset THEN
       "DB_M002_HMI".MaintenanceCounters.Counters[8].WarningBit := FALSE;
   END_IF;
   #Threshold[8] := "DB_M002_HMI".MaintenanceCounters.Counters[8].MaintenanceThreshold * 60;
   #Maintenance[8]("Counter" := "DB_M002_Status"."ISC-CAM".Datacollection.BeltRunTime,   // "FB_ISC-CAM_Maintenance"
                   Threshold := #Threshold[8],
                   Maintenance := "DB_M002_HMI".MaintenanceCounters.Counters[8].WarningBit,
                   CountUnitlNextMaintenance => "DB_M002_HMI".MaintenanceCounters.Counters[8].MaintenanceCountUnitlNextMaintenance);
END_REGION

REGION Network 11: Maintenance counter. Pop up cylinder activations - cylinder movement, wear and contaminants, zone 2
   RUNG wire#powerrail
      Contact( "DB_M002_HMI".MaintenanceCounters.Counters[9].WarningBit )
      Contact( "DB_M002_HMI".MaintenanceCounters.Counters[9].Reset )
      R_Coil( "DB_M002_HMI".MaintenanceCounters.Counters[9].WarningBit )
   END_RUNG
   RUNG wire#powerrail
      Mul(in1 := "DB_M002_HMI".MaintenanceCounters.Counters[9].MaintenanceThreshold, in2 := 60, out => #Threshold[9])
      #Maintenance[9]("Counter" := "DB_M002_Status"."ISC-CAM".Datacollection.BeltRunTime, Threshold := #Threshold[9], Maintenance := "DB_M002_HMI".MaintenanceCounters.Counters[9].WarningBit, CountUnitlNextMaintenance => "DB_M002_HMI".MaintenanceCounters.Counters[9].MaintenanceCountUnitlNextMaintenance)
   END_RUNG
   // the same network as SCL:
   IF "DB_M002_HMI".MaintenanceCounters.Counters[9].WarningBit AND "DB_M002_HMI".MaintenanceCounters.Counters[9].Reset THEN
       "DB_M002_HMI".MaintenanceCounters.Counters[9].WarningBit := FALSE;
   END_IF;
   #Threshold[9] := "DB_M002_HMI".MaintenanceCounters.Counters[9].MaintenanceThreshold * 60;
   #Maintenance[9]("Counter" := "DB_M002_Status"."ISC-CAM".Datacollection.BeltRunTime,   // "FB_ISC-CAM_Maintenance"
                   Threshold := #Threshold[9],
                   Maintenance := "DB_M002_HMI".MaintenanceCounters.Counters[9].WarningBit,
                   CountUnitlNextMaintenance => "DB_M002_HMI".MaintenanceCounters.Counters[9].MaintenanceCountUnitlNextMaintenance);
END_REGION

REGION Network 12: Maintenance counter. Up time - pneumatic system check.
   RUNG wire#powerrail
      Contact( "DB_M002_HMI".MaintenanceCounters.Counters[10].WarningBit )
      Contact( "DB_M002_HMI".MaintenanceCounters.Counters[10].Reset )
      R_Coil( "DB_M002_HMI".MaintenanceCounters.Counters[10].WarningBit )
   END_RUNG
   RUNG wire#powerrail
      Mul(in1 := "DB_M002_HMI".MaintenanceCounters.Counters[10].MaintenanceThreshold, in2 := 60, out => #Threshold[10])
      #Maintenance[10]("Counter" := "DB_M002_Status"."ISC-CAM".Datacollection.BeltRunTime, Threshold := #Threshold[10], Maintenance := "DB_M002_HMI".MaintenanceCounters.Counters[10].WarningBit, CountUnitlNextMaintenance => "DB_M002_HMI".MaintenanceCounters.Counters[10].MaintenanceCountUnitlNextMaintenance)
   END_RUNG
   // the same network as SCL:
   IF "DB_M002_HMI".MaintenanceCounters.Counters[10].WarningBit AND "DB_M002_HMI".MaintenanceCounters.Counters[10].Reset THEN
       "DB_M002_HMI".MaintenanceCounters.Counters[10].WarningBit := FALSE;
   END_IF;
   #Threshold[10] := "DB_M002_HMI".MaintenanceCounters.Counters[10].MaintenanceThreshold * 60;
   #Maintenance[10]("Counter" := "DB_M002_Status"."ISC-CAM".Datacollection.BeltRunTime,   // "FB_ISC-CAM_Maintenance"
                    Threshold := #Threshold[10],
                    Maintenance := "DB_M002_HMI".MaintenanceCounters.Counters[10].WarningBit,
                    CountUnitlNextMaintenance => "DB_M002_HMI".MaintenanceCounters.Counters[10].MaintenanceCountUnitlNextMaintenance);
END_REGION
END_FUNCTION_BLOCK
